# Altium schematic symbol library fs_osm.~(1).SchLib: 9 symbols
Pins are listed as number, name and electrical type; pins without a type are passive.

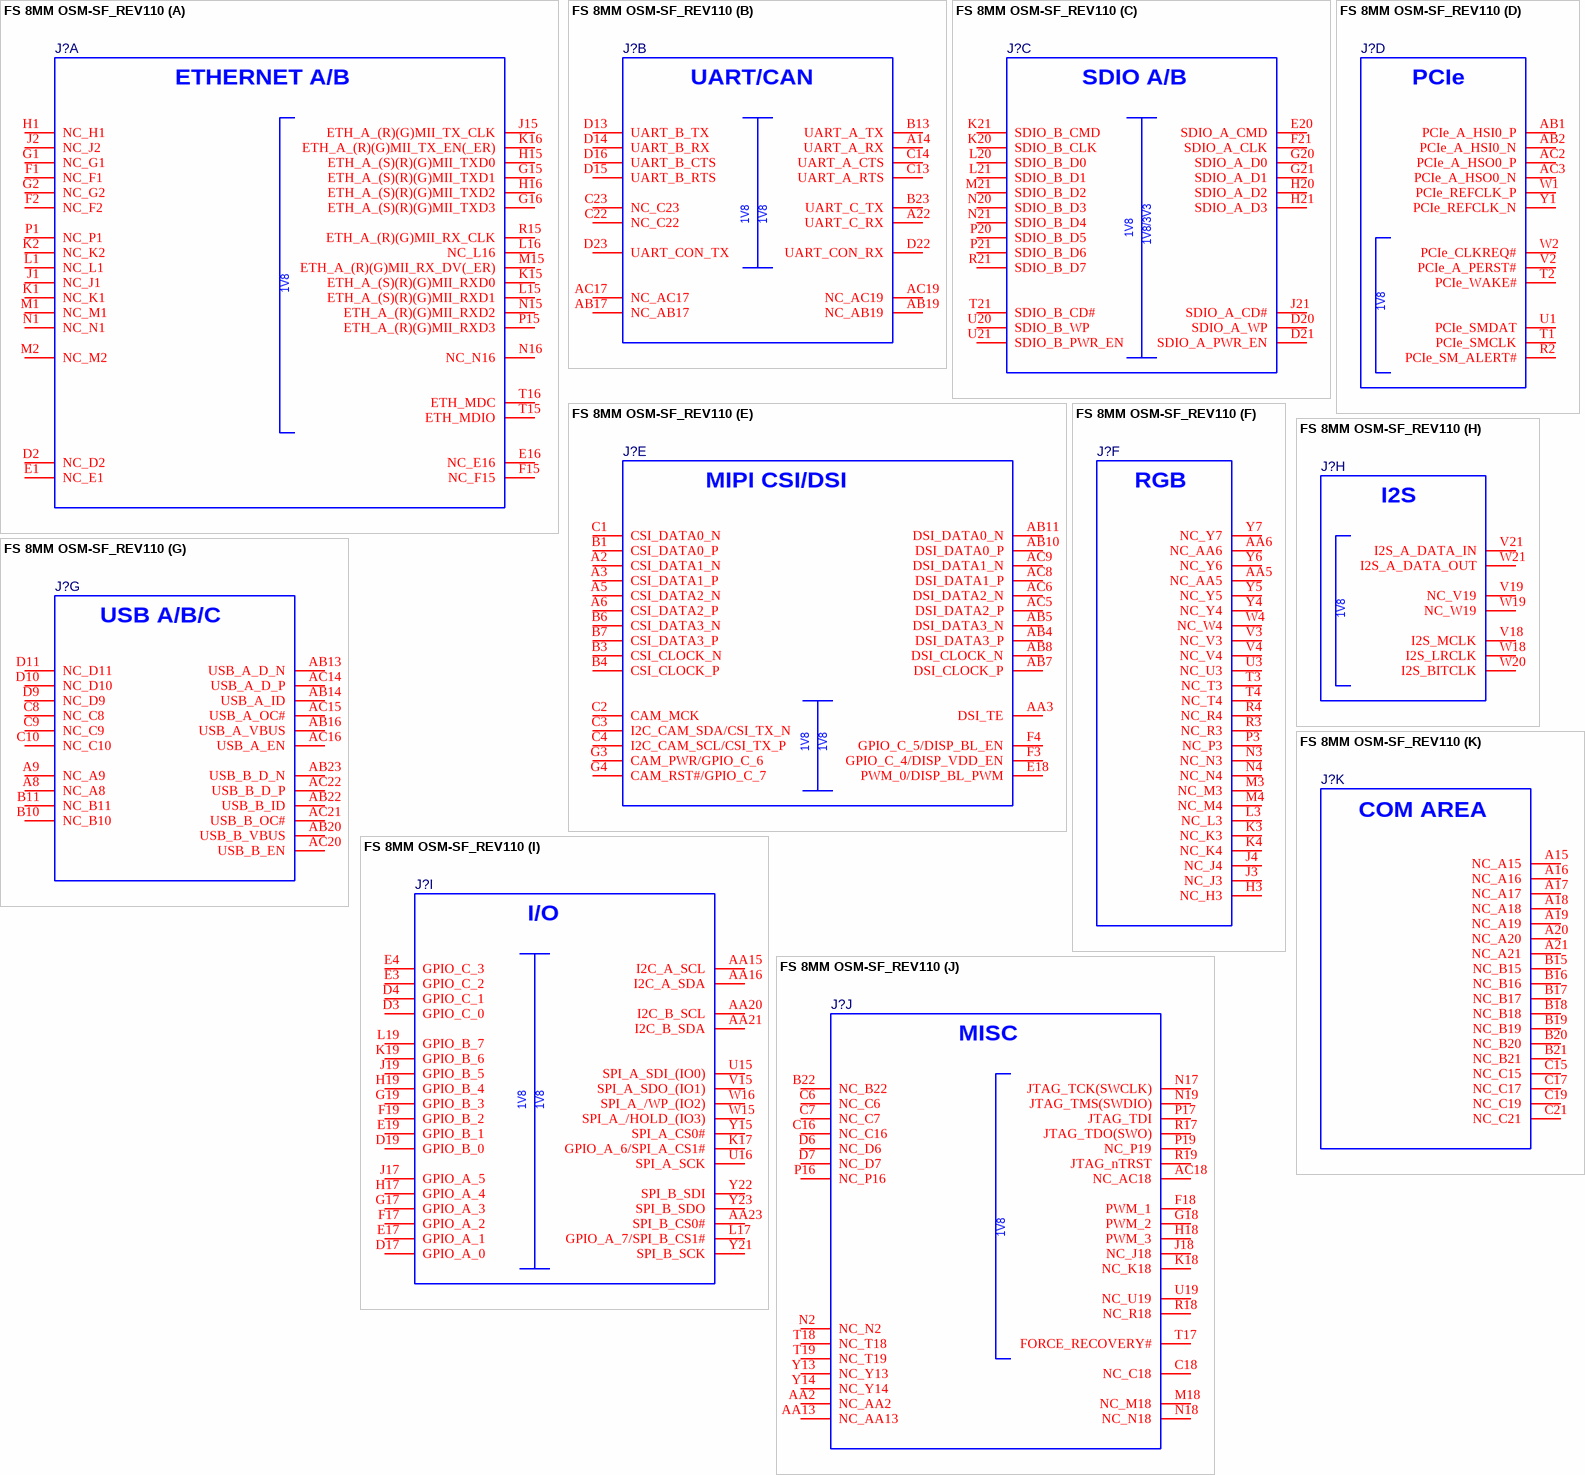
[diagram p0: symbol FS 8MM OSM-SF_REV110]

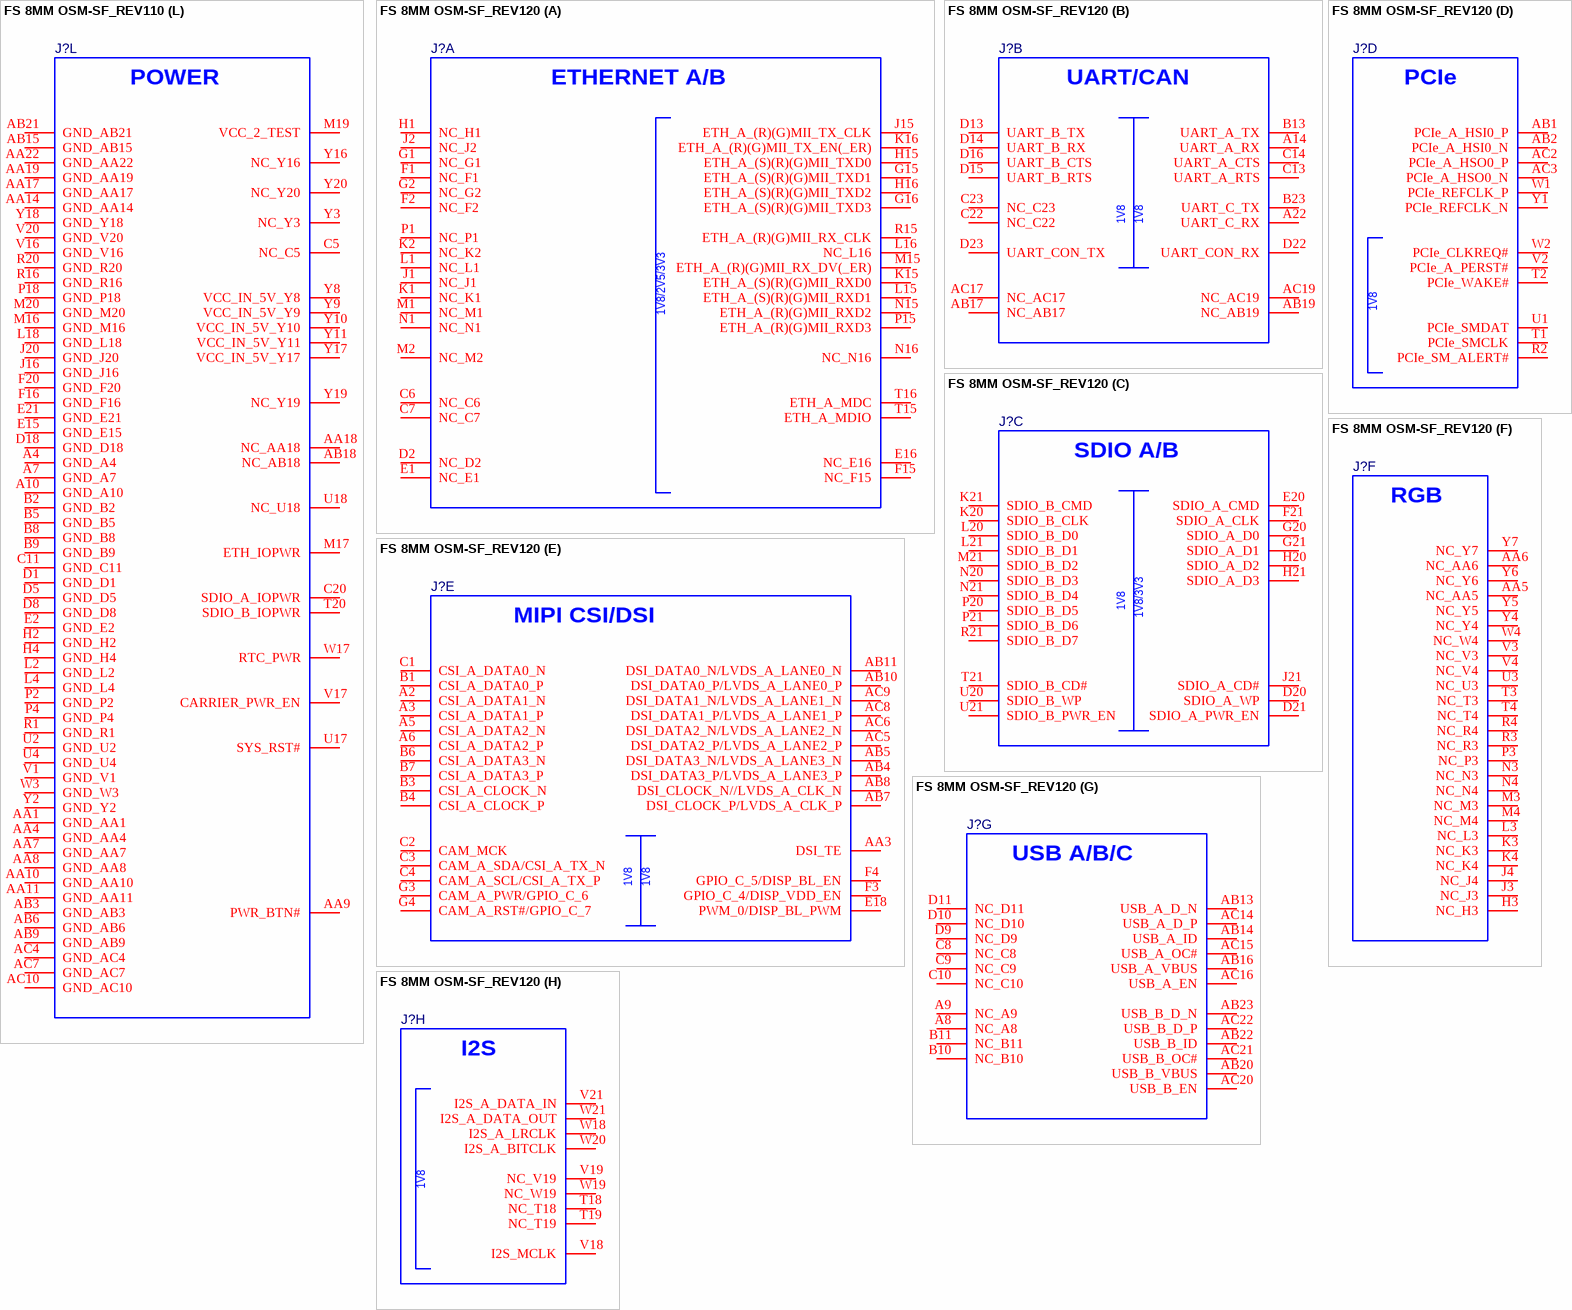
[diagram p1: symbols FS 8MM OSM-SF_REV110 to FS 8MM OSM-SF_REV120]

## FS 8MM OSM-SF_REV110
designator J?  (value not drawn)
part A pins: D2 NC_D2, E1 NC_E1, E16 NC_E16, F1 NC_F1, F2 NC_F2, F15 NC_F15, G1 NC_G1, G2 NC_G2, G15 ETH_A_(S)(R)(G)MII_TXD1, G16 ETH_A_(S)(R)(G)MII_TXD3, H1 NC_H1, H15 ETH_A_(S)(R)(G)MII_TXD0, H16 ETH_A_(S)(R)(G)MII_TXD2, J1 NC_J1, J2 NC_J2, J15 ETH_A_(R)(G)MII_TX_CLK, K1 NC_K1, K2 NC_K2, K15 ETH_A_(S)(R)(G)MII_RXD0, K16 ETH_A_(R)(G)MII_TX_EN(_ER), L1 NC_L1, L15 ETH_A_(S)(R)(G)MII_RXD1, L16 NC_L16, M1 NC_M1, M2 NC_M2, M15 ETH_A_(R)(G)MII_RX_DV(_ER), N1 NC_N1, N15 ETH_A_(R)(G)MII_RXD2, N16 NC_N16, P1 NC_P1, P15 ETH_A_(R)(G)MII_RXD3, R15 ETH_A_(R)(G)MII_RX_CLK, T15 ETH_MDIO, T16 ETH_MDC
part B pins: A14 UART_A_RX, A22 UART_C_RX, AB17 NC_AB17, AB19 NC_AB19, AC17 NC_AC17, AC19 NC_AC19, B13 UART_A_TX, B23 UART_C_TX, C13 UART_A_RTS, C14 UART_A_CTS, C22 NC_C22, C23 NC_C23, D13 UART_B_TX, D14 UART_B_RX, D15 UART_B_RTS, D16 UART_B_CTS, D22 UART_CON_RX, D23 UART_CON_TX
part C pins: D20 SDIO_A_WP, D21 SDIO_A_PWR_EN, E20 SDIO_A_CMD, F21 SDIO_A_CLK, G20 SDIO_A_D0, G21 SDIO_A_D1, H20 SDIO_A_D2, H21 SDIO_A_D3, J21 SDIO_A_CD#, K20 SDIO_B_CLK, K21 SDIO_B_CMD, L20 SDIO_B_D0, L21 SDIO_B_D1, M21 SDIO_B_D2, N20 SDIO_B_D3, N21 SDIO_B_D4, P20 SDIO_B_D5, P21 SDIO_B_D6, R21 SDIO_B_D7, T21 SDIO_B_CD#, U20 SDIO_B_WP, U21 SDIO_B_PWR_EN
part D pins: AB1 PCIe_A_HSI0_P, AB2 PCIe_A_HSI0_N, AC2 PCIe_A_HSO0_P, AC3 PCIe_A_HSO0_N, R2 PCIe_SM_ALERT#, T1 PCIe_SMCLK, T2 PCIe_WAKE#, U1 PCIe_SMDAT, V2 PCIe_A_PERST#, W1 PCIe_REFCLK_P, W2 PCIe_CLKREQ#, Y1 PCIe_REFCLK_N
part E pins: A2 CSI_DATA1_N, A3 CSI_DATA1_P, A5 CSI_DATA2_N, A6 CSI_DATA2_P, AA3 DSI_TE, AB4 DSI_DATA3_P, AB5 DSI_DATA3_N, AB7 DSI_CLOCK_P, AB8 DSI_CLOCK_N, AB10 DSI_DATA0_P, AB11 DSI_DATA0_N, AC5 DSI_DATA2_P, AC6 DSI_DATA2_N, AC8 DSI_DATA1_P, AC9 DSI_DATA1_N, B1 CSI_DATA0_P, B3 CSI_CLOCK_N, B4 CSI_CLOCK_P, B6 CSI_DATA3_N, B7 CSI_DATA3_P, C1 CSI_DATA0_N, C2 CAM_MCK, C3 I2C_CAM_SDA/CSI_TX_N, C4 I2C_CAM_SCL/CSI_TX_P, E18 PWM_0/DISP_BL_PWM, F3 GPIO_C_4/DISP_VDD_EN, F4 GPIO_C_5/DISP_BL_EN, G3 CAM_PWR/GPIO_C_6, G4 CAM_RST#/GPIO_C_7
part F pins: AA5 NC_AA5, AA6 NC_AA6, H3 NC_H3, J3 NC_J3, J4 NC_J4, K3 NC_K3, K4 NC_K4, L3 NC_L3, M3 NC_M3, M4 NC_M4, N3 NC_N3, N4 NC_N4, P3 NC_P3, R3 NC_R3, R4 NC_R4, T3 NC_T3, T4 NC_T4, U3 NC_U3, V3 NC_V3, V4 NC_V4, W4 NC_W4, Y4 NC_Y4, Y5 NC_Y5, Y6 NC_Y6, Y7 NC_Y7
part G pins: A8 NC_A8, A9 NC_A9, AB13 USB_A_D_N, AB14 USB_A_ID, AB16 USB_A_VBUS, AB20 USB_B_VBUS, AB22 USB_B_ID, AB23 USB_B_D_N, AC14 USB_A_D_P, AC15 USB_A_OC#, AC16 USB_A_EN, AC20 USB_B_EN, AC21 USB_B_OC#, AC22 USB_B_D_P, B10 NC_B10, B11 NC_B11, C8 NC_C8, C9 NC_C9, C10 NC_C10, D9 NC_D9, D10 NC_D10, D11 NC_D11
part H pins: V18 I2S_MCLK, V19 NC_V19, V21 I2S_A_DATA_IN, W18 I2S_LRCLK, W19 NC_W19, W20 I2S_BITCLK, W21 I2S_A_DATA_OUT
part I pins: AA15 I2C_A_SCL, AA16 I2C_A_SDA, AA20 I2C_B_SCL, AA21 I2C_B_SDA, AA23 SPI_B_CS0#, D3 GPIO_C_0, D4 GPIO_C_1, D17 GPIO_A_0, D19 GPIO_B_0, E3 GPIO_C_2, E4 GPIO_C_3, E17 GPIO_A_1, E19 GPIO_B_1, F17 GPIO_A_2, F19 GPIO_B_2, G17 GPIO_A_3, G19 GPIO_B_3, H17 GPIO_A_4, H19 GPIO_B_4, J17 GPIO_A_5, J19 GPIO_B_5, K17 GPIO_A_6/SPI_A_CS1#, K19 GPIO_B_6, L17 GPIO_A_7/SPI_B_CS1#, L19 GPIO_B_7, U15 SPI_A_SDI_(IO0), U16 SPI_A_SCK, V15 SPI_A_SDO_(IO1), W15 SPI_A_/HOLD_(IO3), W16 SPI_A_/WP_(IO2), Y15 SPI_A_CS0#, Y21 SPI_B_SCK, Y22 SPI_B_SDI, Y23 SPI_B_SDO
part J pins: AA2 NC_AA2, AA13 NC_AA13, AC18 NC_AC18, B22 NC_B22, C6 NC_C6, C7 NC_C7, C16 NC_C16, C18 NC_C18, D6 NC_D6, D7 NC_D7, F18 PWM_1, G18 PWM_2, H18 PWM_3, J18 NC_J18, K18 NC_K18, M18 NC_M18, N2 NC_N2, N17 JTAG_TCK(SWCLK), N18 NC_N18, N19 JTAG_TMS(SWDIO), P16 NC_P16, P17 JTAG_TDI, P19 NC_P19, R17 JTAG_TDO(SWO), R18 NC_R18, R19 JTAG_nTRST, T17 FORCE_RECOVERY#, T18 NC_T18, T19 NC_T19, U19 NC_U19, Y13 NC_Y13, Y14 NC_Y14
part K pins: A15 NC_A15, A16 NC_A16, A17 NC_A17, A18 NC_A18, A19 NC_A19, A20 NC_A20, A21 NC_A21, B15 NC_B15, B16 NC_B16, B17 NC_B17, B18 NC_B18, B19 NC_B19, B20 NC_B20, B21 NC_B21, C15 NC_C15, C17 NC_C17, C19 NC_C19, C21 NC_C21
part L pins: A4 GND_A4 (power), A7 GND_A7 (power), A10 GND_A10 (power), AA1 GND_AA1 (power), AA4 GND_AA4 (power), AA7 GND_AA7 (power), AA8 GND_AA8 (power), AA9 PWR_BTN#, AA10 GND_AA10 (power), AA11 GND_AA11 (power), AA14 GND_AA14 (power), AA17 GND_AA17 (power), AA18 NC_AA18, AA19 GND_AA19 (power), AA22 GND_AA22 (power), AB3 GND_AB3 (power), AB6 GND_AB6 (power), AB9 GND_AB9 (power), AB15 GND_AB15 (power), AB18 NC_AB18, AB21 GND_AB21 (power), AC4 GND_AC4 (power), AC7 GND_AC7 (power), AC10 GND_AC10 (power), B2 GND_B2 (power), B5 GND_B5 (power), B8 GND_B8 (power), B9 GND_B9 (power), C5 NC_C5, C11 GND_C11 (power), C20 SDIO_A_IOPWR, D1 GND_D1 (power), D5 GND_D5 (power), D8 GND_D8 (power), D18 GND_D18 (power), E2 GND_E2 (power), E15 GND_E15 (power), E21 GND_E21 (power), F16 GND_F16 (power), F20 GND_F20 (power), H2 GND_H2 (power), H4 GND_H4 (power), J16 GND_J16 (power), J20 GND_J20 (power), L2 GND_L2 (power), L4 GND_L4 (power), L18 GND_L18 (power), M16 GND_M16 (power), M17 ETH_IOPWR (power), M19 VCC_2_TEST, M20 GND_M20 (power), P2 GND_P2 (power), P4 GND_P4 (power), P18 GND_P18 (power), R1 GND_R1 (power), R16 GND_R16 (power), R20 GND_R20 (power), T20 SDIO_B_IOPWR, U2 GND_U2 (power), U4 GND_U4 (power), U17 SYS_RST#, U18 NC_U18, V1 GND_V1 (power), V16 GND_V16 (power), V17 CARRIER_PWR_EN, V20 GND_V20 (power), W3 GND_W3 (power), W17 RTC_PWR (power), Y2 GND_Y2 (power), Y3 NC_Y3, Y8 VCC_IN_5V_Y8 (power), Y9 VCC_IN_5V_Y9 (power), Y10 VCC_IN_5V_Y10 (power), Y11 VCC_IN_5V_Y11 (power), Y16 NC_Y16, Y17 VCC_IN_5V_Y17 (power), Y18 GND_Y18 (power), Y19 NC_Y19, Y20 NC_Y20

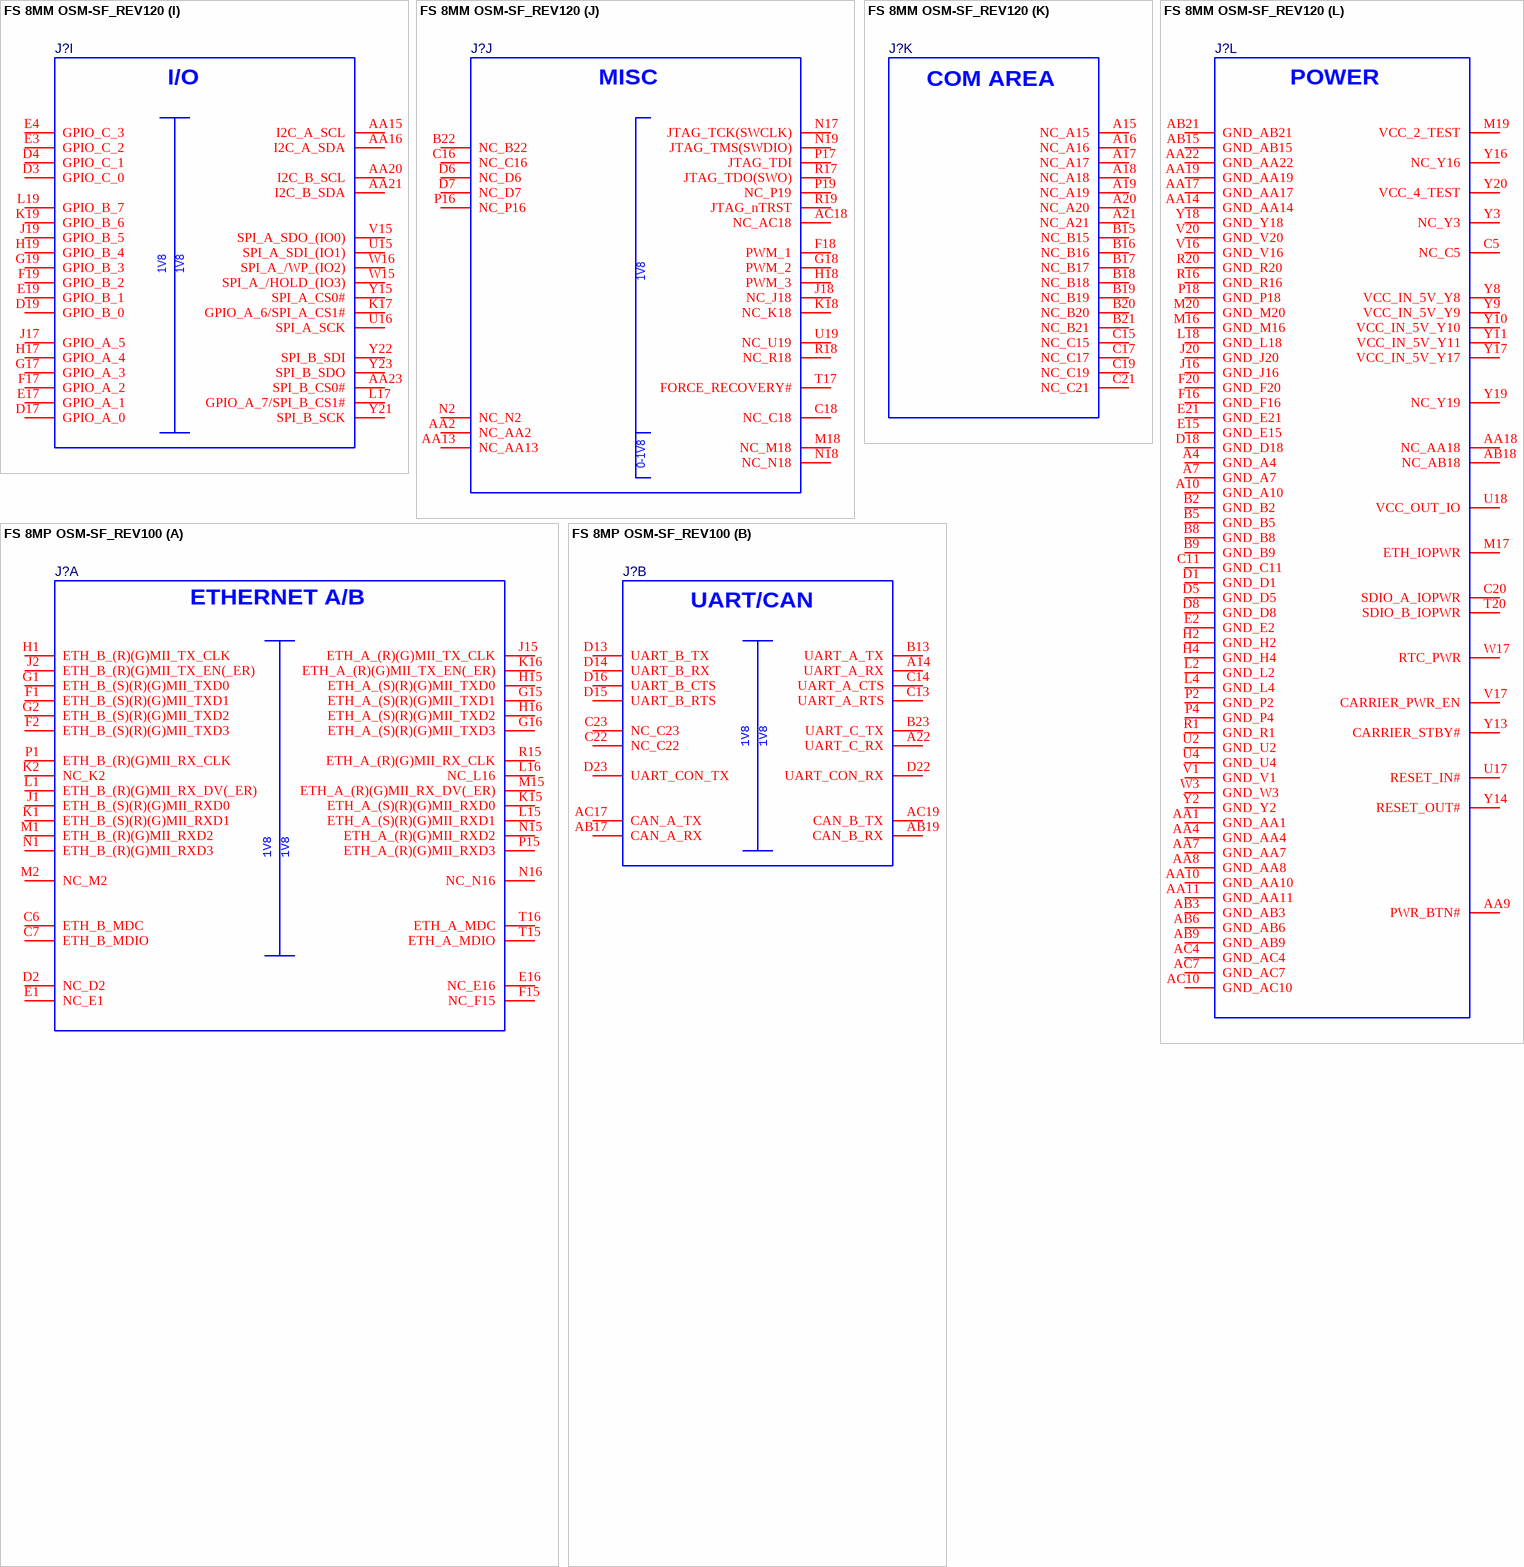
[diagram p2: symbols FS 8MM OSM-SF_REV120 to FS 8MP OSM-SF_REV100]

## FS 8MM OSM-SF_REV120
designator J?  (value not drawn)
part A pins: C6 NC_C6, C7 NC_C7, D2 NC_D2, E1 NC_E1, E16 NC_E16, F1 NC_F1, F2 NC_F2, F15 NC_F15, G1 NC_G1, G2 NC_G2, G15 ETH_A_(S)(R)(G)MII_TXD1, G16 ETH_A_(S)(R)(G)MII_TXD3, H1 NC_H1, H15 ETH_A_(S)(R)(G)MII_TXD0, H16 ETH_A_(S)(R)(G)MII_TXD2, J1 NC_J1, J2 NC_J2, J15 ETH_A_(R)(G)MII_TX_CLK, K1 NC_K1, K2 NC_K2, K15 ETH_A_(S)(R)(G)MII_RXD0, K16 ETH_A_(R)(G)MII_TX_EN(_ER), L1 NC_L1, L15 ETH_A_(S)(R)(G)MII_RXD1, L16 NC_L16, M1 NC_M1, M2 NC_M2, M15 ETH_A_(R)(G)MII_RX_DV(_ER), N1 NC_N1, N15 ETH_A_(R)(G)MII_RXD2, N16 NC_N16, P1 NC_P1, P15 ETH_A_(R)(G)MII_RXD3, R15 ETH_A_(R)(G)MII_RX_CLK, T15 ETH_A_MDIO, T16 ETH_A_MDC
part B pins: A14 UART_A_RX, A22 UART_C_RX, AB17 NC_AB17, AB19 NC_AB19, AC17 NC_AC17, AC19 NC_AC19, B13 UART_A_TX, B23 UART_C_TX, C13 UART_A_RTS, C14 UART_A_CTS, C22 NC_C22, C23 NC_C23, D13 UART_B_TX, D14 UART_B_RX, D15 UART_B_RTS, D16 UART_B_CTS, D22 UART_CON_RX, D23 UART_CON_TX
part C pins: D20 SDIO_A_WP, D21 SDIO_A_PWR_EN, E20 SDIO_A_CMD, F21 SDIO_A_CLK, G20 SDIO_A_D0, G21 SDIO_A_D1, H20 SDIO_A_D2, H21 SDIO_A_D3, J21 SDIO_A_CD#, K20 SDIO_B_CLK, K21 SDIO_B_CMD, L20 SDIO_B_D0, L21 SDIO_B_D1, M21 SDIO_B_D2, N20 SDIO_B_D3, N21 SDIO_B_D4, P20 SDIO_B_D5, P21 SDIO_B_D6, R21 SDIO_B_D7, T21 SDIO_B_CD#, U20 SDIO_B_WP, U21 SDIO_B_PWR_EN
part D pins: AB1 PCIe_A_HSI0_P, AB2 PCIe_A_HSI0_N, AC2 PCIe_A_HSO0_P, AC3 PCIe_A_HSO0_N, R2 PCIe_SM_ALERT#, T1 PCIe_SMCLK, T2 PCIe_WAKE#, U1 PCIe_SMDAT, V2 PCIe_A_PERST#, W1 PCIe_REFCLK_P, W2 PCIe_CLKREQ#, Y1 PCIe_REFCLK_N
part E pins: A2 CSI_A_DATA1_N, A3 CSI_A_DATA1_P, A5 CSI_A_DATA2_N, A6 CSI_A_DATA2_P, AA3 DSI_TE, AB4 DSI_DATA3_P/LVDS_A_LANE3_P, AB5 DSI_DATA3_N/LVDS_A_LANE3_N, AB7 DSI_CLOCK_P/LVDS_A_CLK_P, AB8 DSI_CLOCK_N//LVDS_A_CLK_N, AB10 DSI_DATA0_P/LVDS_A_LANE0_P, AB11 DSI_DATA0_N/LVDS_A_LANE0_N, AC5 DSI_DATA2_P/LVDS_A_LANE2_P, AC6 DSI_DATA2_N/LVDS_A_LANE2_N, AC8 DSI_DATA1_P/LVDS_A_LANE1_P, AC9 DSI_DATA1_N/LVDS_A_LANE1_N, B1 CSI_A_DATA0_P, B3 CSI_A_CLOCK_N, B4 CSI_A_CLOCK_P, B6 CSI_A_DATA3_N, B7 CSI_A_DATA3_P, C1 CSI_A_DATA0_N, C2 CAM_MCK, C3 CAM_A_SDA/CSI_A_TX_N, C4 CAM_A_SCL/CSI_A_TX_P, E18 PWM_0/DISP_BL_PWM, F3 GPIO_C_4/DISP_VDD_EN, F4 GPIO_C_5/DISP_BL_EN, G3 CAM_A_PWR/GPIO_C_6, G4 CAM_A_RST#/GPIO_C_7
part F pins: AA5 NC_AA5, AA6 NC_AA6, H3 NC_H3, J3 NC_J3, J4 NC_J4, K3 NC_K3, K4 NC_K4, L3 NC_L3, M3 NC_M3, M4 NC_M4, N3 NC_N3, N4 NC_N4, P3 NC_P3, R3 NC_R3, R4 NC_R4, T3 NC_T3, T4 NC_T4, U3 NC_U3, V3 NC_V3, V4 NC_V4, W4 NC_W4, Y4 NC_Y4, Y5 NC_Y5, Y6 NC_Y6, Y7 NC_Y7
part G pins: A8 NC_A8, A9 NC_A9, AB13 USB_A_D_N, AB14 USB_A_ID, AB16 USB_A_VBUS, AB20 USB_B_VBUS, AB22 USB_B_ID, AB23 USB_B_D_N, AC14 USB_A_D_P, AC15 USB_A_OC#, AC16 USB_A_EN, AC20 USB_B_EN, AC21 USB_B_OC#, AC22 USB_B_D_P, B10 NC_B10, B11 NC_B11, C8 NC_C8, C9 NC_C9, C10 NC_C10, D9 NC_D9, D10 NC_D10, D11 NC_D11
part H pins: T18 NC_T18, T19 NC_T19, V18 I2S_MCLK, V19 NC_V19, V21 I2S_A_DATA_IN, W18 I2S_A_LRCLK, W19 NC_W19, W20 I2S_A_BITCLK, W21 I2S_A_DATA_OUT
part I pins: AA15 I2C_A_SCL, AA16 I2C_A_SDA, AA20 I2C_B_SCL, AA21 I2C_B_SDA, AA23 SPI_B_CS0#, D3 GPIO_C_0, D4 GPIO_C_1, D17 GPIO_A_0, D19 GPIO_B_0, E3 GPIO_C_2, E4 GPIO_C_3, E17 GPIO_A_1, E19 GPIO_B_1, F17 GPIO_A_2, F19 GPIO_B_2, G17 GPIO_A_3, G19 GPIO_B_3, H17 GPIO_A_4, H19 GPIO_B_4, J17 GPIO_A_5, J19 GPIO_B_5, K17 GPIO_A_6/SPI_A_CS1#, K19 GPIO_B_6, L17 GPIO_A_7/SPI_B_CS1#, L19 GPIO_B_7, U15 SPI_A_SDI_(IO1), U16 SPI_A_SCK, V15 SPI_A_SDO_(IO0), W15 SPI_A_/HOLD_(IO3), W16 SPI_A_/WP_(IO2), Y15 SPI_A_CS0#, Y21 SPI_B_SCK, Y22 SPI_B_SDI, Y23 SPI_B_SDO
part J pins: AA2 NC_AA2, AA13 NC_AA13, AC18 NC_AC18, B22 NC_B22, C16 NC_C16, C18 NC_C18, D6 NC_D6, D7 NC_D7, F18 PWM_1, G18 PWM_2, H18 PWM_3, J18 NC_J18, K18 NC_K18, M18 NC_M18, N2 NC_N2, N17 JTAG_TCK(SWCLK), N18 NC_N18, N19 JTAG_TMS(SWDIO), P16 NC_P16, P17 JTAG_TDI, P19 NC_P19, R17 JTAG_TDO(SWO), R18 NC_R18, R19 JTAG_nTRST, T17 FORCE_RECOVERY#, U19 NC_U19
part K pins: A15 NC_A15, A16 NC_A16, A17 NC_A17, A18 NC_A18, A19 NC_A19, A20 NC_A20, A21 NC_A21, B15 NC_B15, B16 NC_B16, B17 NC_B17, B18 NC_B18, B19 NC_B19, B20 NC_B20, B21 NC_B21, C15 NC_C15, C17 NC_C17, C19 NC_C19, C21 NC_C21
part L pins: A4 GND_A4 (power), A7 GND_A7 (power), A10 GND_A10 (power), AA1 GND_AA1 (power), AA4 GND_AA4 (power), AA7 GND_AA7 (power), AA8 GND_AA8 (power), AA9 PWR_BTN#, AA10 GND_AA10 (power), AA11 GND_AA11 (power), AA14 GND_AA14 (power), AA17 GND_AA17 (power), AA18 NC_AA18, AA19 GND_AA19 (power), AA22 GND_AA22 (power), AB3 GND_AB3 (power), AB6 GND_AB6 (power), AB9 GND_AB9 (power), AB15 GND_AB15 (power), AB18 NC_AB18, AB21 GND_AB21 (power), AC4 GND_AC4 (power), AC7 GND_AC7 (power), AC10 GND_AC10 (power), B2 GND_B2 (power), B5 GND_B5 (power), B8 GND_B8 (power), B9 GND_B9 (power), C5 NC_C5, C11 GND_C11 (power), C20 SDIO_A_IOPWR, D1 GND_D1 (power), D5 GND_D5 (power), D8 GND_D8 (power), D18 GND_D18 (power), E2 GND_E2 (power), E15 GND_E15 (power), E21 GND_E21 (power), F16 GND_F16 (power), F20 GND_F20 (power), H2 GND_H2 (power), H4 GND_H4 (power), J16 GND_J16 (power), J20 GND_J20 (power), L2 GND_L2 (power), L4 GND_L4 (power), L18 GND_L18 (power), M16 GND_M16 (power), M17 ETH_IOPWR (power), M19 VCC_2_TEST, M20 GND_M20 (power), P2 GND_P2 (power), P4 GND_P4 (power), P18 GND_P18 (power), R1 GND_R1 (power), R16 GND_R16 (power), R20 GND_R20 (power), T20 SDIO_B_IOPWR, U2 GND_U2 (power), U4 GND_U4 (power), U17 RESET_IN#, U18 VCC_OUT_IO, V1 GND_V1 (power), V16 GND_V16 (power), V17 CARRIER_PWR_EN, V20 GND_V20 (power), W3 GND_W3 (power), W17 RTC_PWR (power), Y2 GND_Y2 (power), Y3 NC_Y3, Y8 VCC_IN_5V_Y8 (power), Y9 VCC_IN_5V_Y9 (power), Y10 VCC_IN_5V_Y10 (power), Y11 VCC_IN_5V_Y11 (power), Y13 CARRIER_STBY#, Y14 RESET_OUT#, Y16 NC_Y16, Y17 VCC_IN_5V_Y17 (power), Y18 GND_Y18 (power), Y19 NC_Y19, Y20 VCC_4_TEST

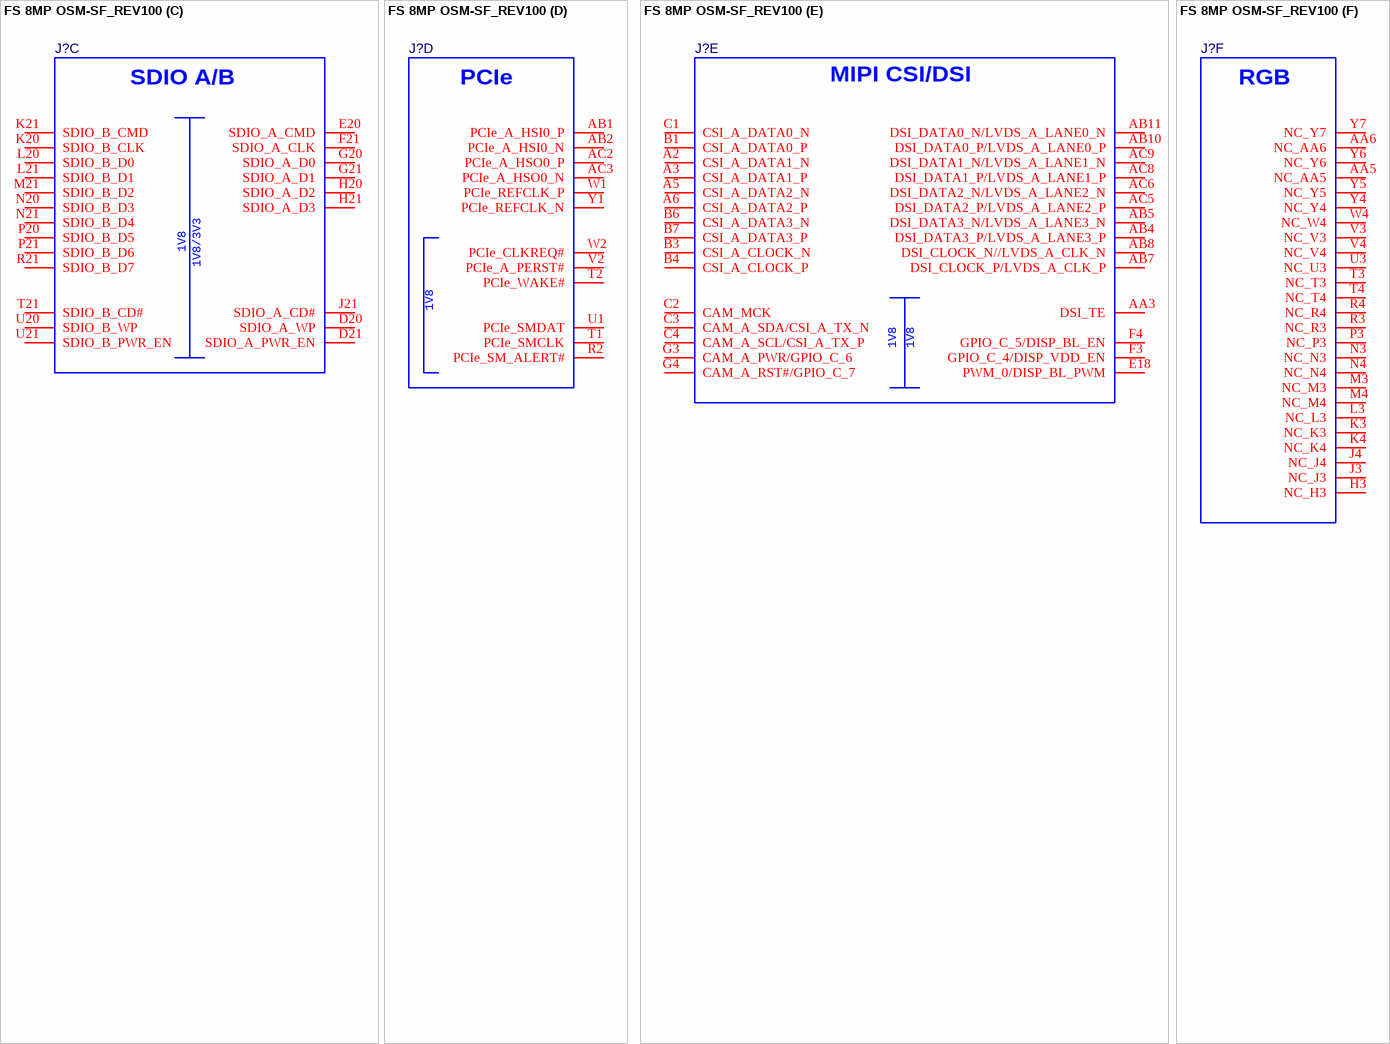
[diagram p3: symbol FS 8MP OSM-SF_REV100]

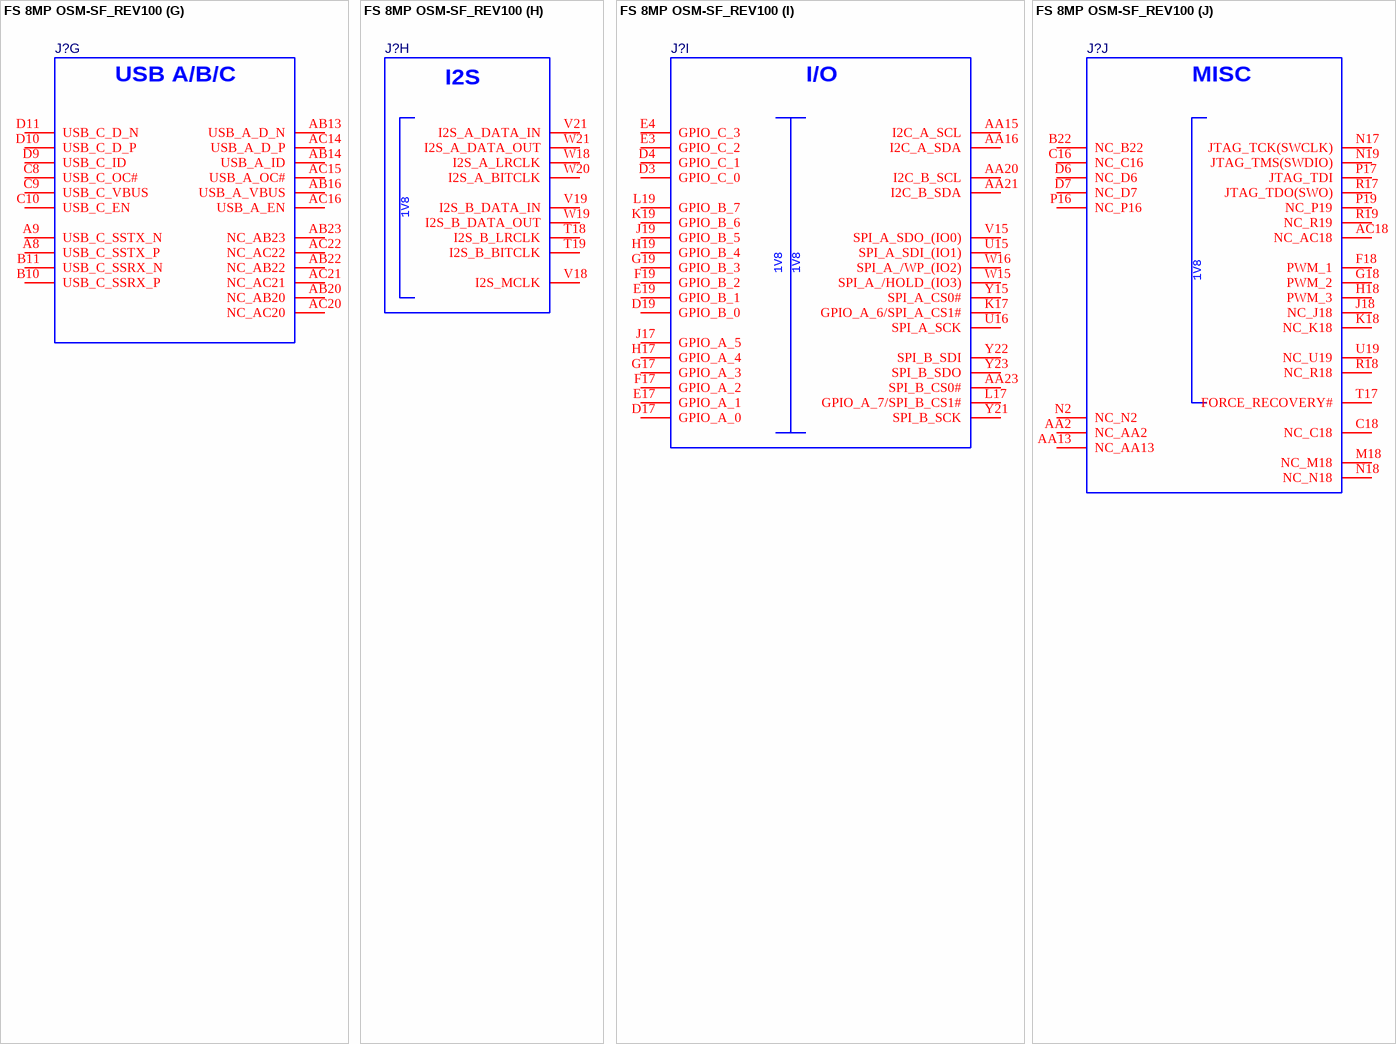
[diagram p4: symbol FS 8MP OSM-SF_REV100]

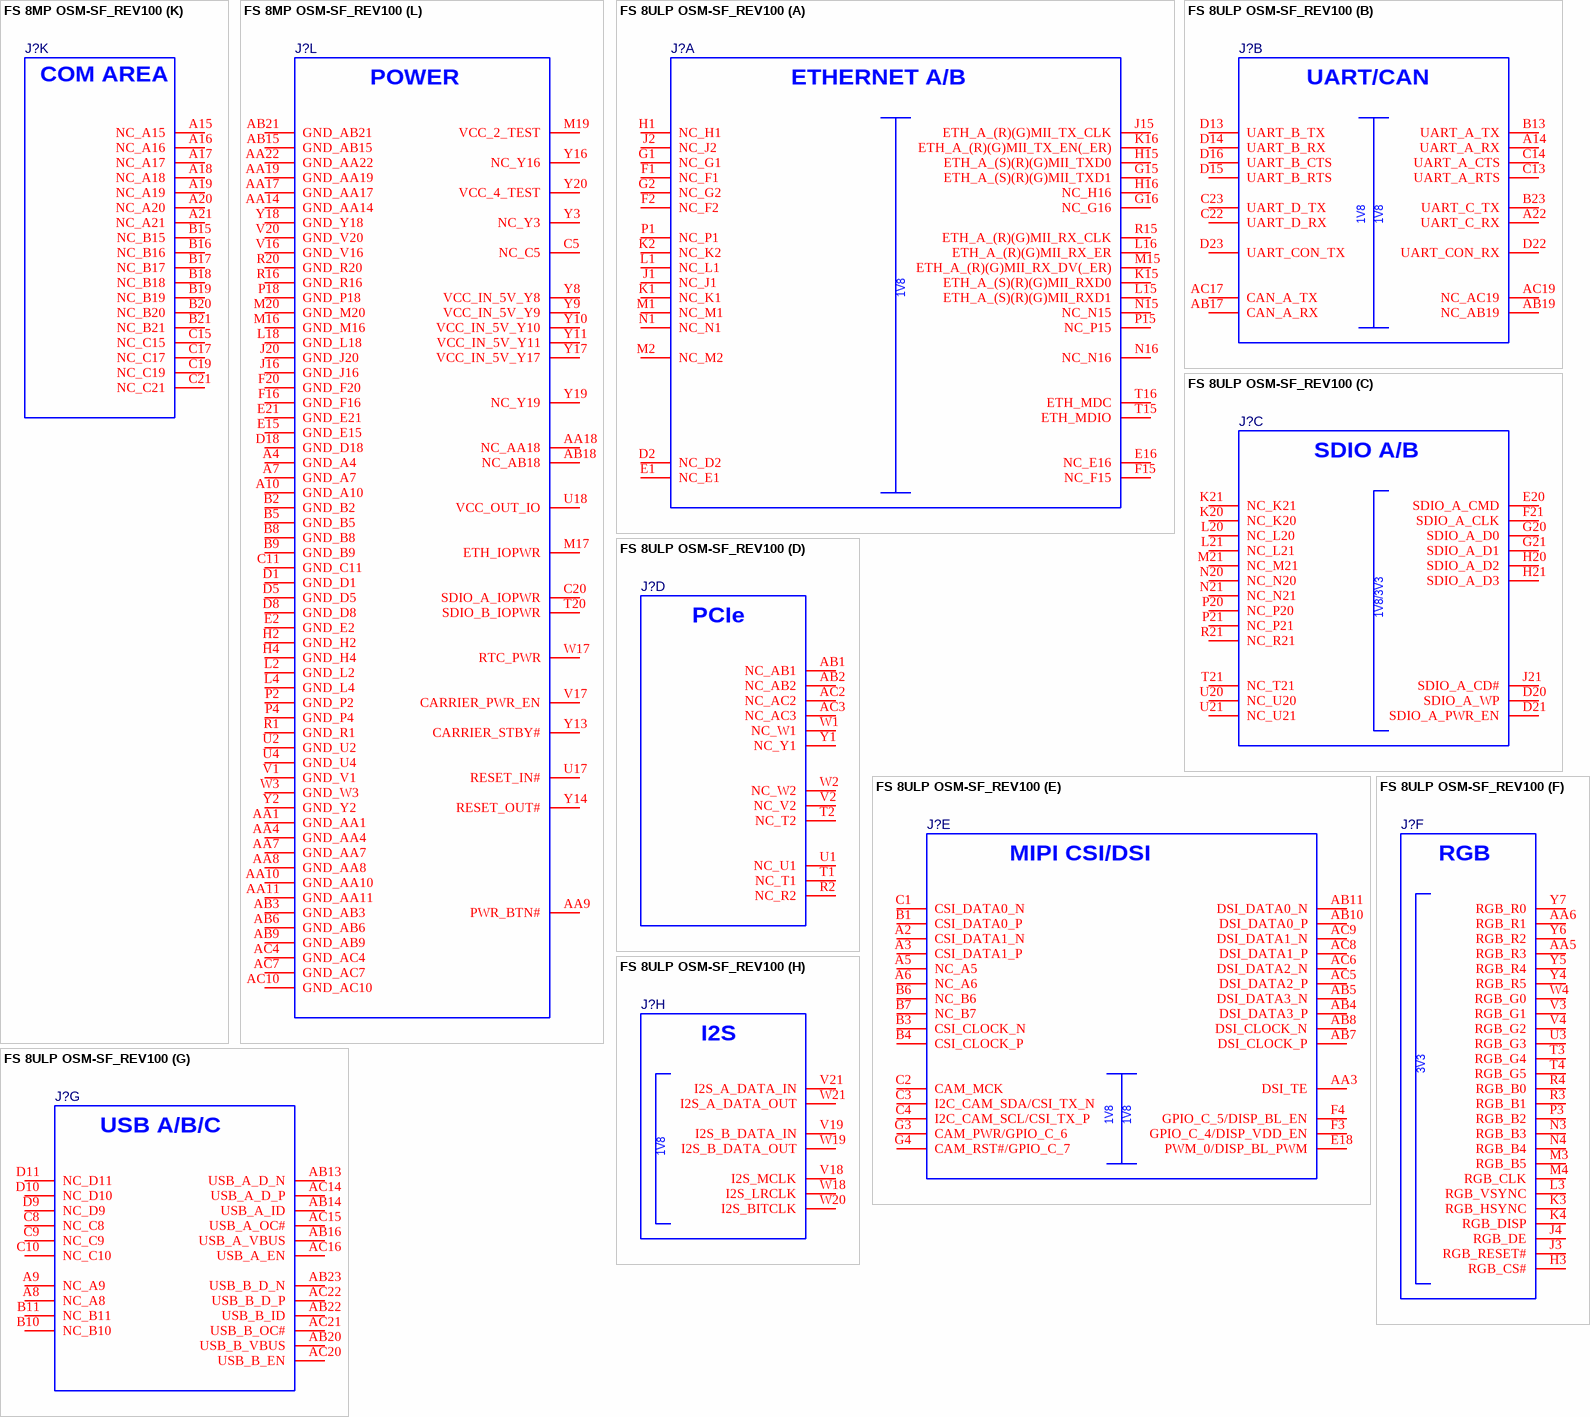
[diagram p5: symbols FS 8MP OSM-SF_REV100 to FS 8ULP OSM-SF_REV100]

## FS 8MP OSM-SF_REV100
designator J?  (value not drawn)
part A pins: C6 ETH_B_MDC, C7 ETH_B_MDIO, D2 NC_D2, E1 NC_E1, E16 NC_E16, F1 ETH_B_(S)(R)(G)MII_TXD1, F2 ETH_B_(S)(R)(G)MII_TXD3, F15 NC_F15, G1 ETH_B_(S)(R)(G)MII_TXD0, G2 ETH_B_(S)(R)(G)MII_TXD2, G15 ETH_A_(S)(R)(G)MII_TXD1, G16 ETH_A_(S)(R)(G)MII_TXD3, H1 ETH_B_(R)(G)MII_TX_CLK, H15 ETH_A_(S)(R)(G)MII_TXD0, H16 ETH_A_(S)(R)(G)MII_TXD2, J1 ETH_B_(S)(R)(G)MII_RXD0, J2 ETH_B_(R)(G)MII_TX_EN(_ER), J15 ETH_A_(R)(G)MII_TX_CLK, K1 ETH_B_(S)(R)(G)MII_RXD1, K2 NC_K2, K15 ETH_A_(S)(R)(G)MII_RXD0, K16 ETH_A_(R)(G)MII_TX_EN(_ER), L1 ETH_B_(R)(G)MII_RX_DV(_ER), L15 ETH_A_(S)(R)(G)MII_RXD1, L16 NC_L16, M1 ETH_B_(R)(G)MII_RXD2, M2 NC_M2, M15 ETH_A_(R)(G)MII_RX_DV(_ER), N1 ETH_B_(R)(G)MII_RXD3, N15 ETH_A_(R)(G)MII_RXD2, N16 NC_N16, P1 ETH_B_(R)(G)MII_RX_CLK, P15 ETH_A_(R)(G)MII_RXD3, R15 ETH_A_(R)(G)MII_RX_CLK, T15 ETH_A_MDIO, T16 ETH_A_MDC
part B pins: A14 UART_A_RX, A22 UART_C_RX, AB17 CAN_A_RX, AB19 CAN_B_RX, AC17 CAN_A_TX, AC19 CAN_B_TX, B13 UART_A_TX, B23 UART_C_TX, C13 UART_A_RTS, C14 UART_A_CTS, C22 NC_C22, C23 NC_C23, D13 UART_B_TX, D14 UART_B_RX, D15 UART_B_RTS, D16 UART_B_CTS, D22 UART_CON_RX, D23 UART_CON_TX
part C pins: D20 SDIO_A_WP, D21 SDIO_A_PWR_EN, E20 SDIO_A_CMD, F21 SDIO_A_CLK, G20 SDIO_A_D0, G21 SDIO_A_D1, H20 SDIO_A_D2, H21 SDIO_A_D3, J21 SDIO_A_CD#, K20 SDIO_B_CLK, K21 SDIO_B_CMD, L20 SDIO_B_D0, L21 SDIO_B_D1, M21 SDIO_B_D2, N20 SDIO_B_D3, N21 SDIO_B_D4, P20 SDIO_B_D5, P21 SDIO_B_D6, R21 SDIO_B_D7, T21 SDIO_B_CD#, U20 SDIO_B_WP, U21 SDIO_B_PWR_EN
part D pins: AB1 PCIe_A_HSI0_P, AB2 PCIe_A_HSI0_N, AC2 PCIe_A_HSO0_P, AC3 PCIe_A_HSO0_N, R2 PCIe_SM_ALERT#, T1 PCIe_SMCLK, T2 PCIe_WAKE#, U1 PCIe_SMDAT, V2 PCIe_A_PERST#, W1 PCIe_REFCLK_P, W2 PCIe_CLKREQ#, Y1 PCIe_REFCLK_N
part E pins: A2 CSI_A_DATA1_N, A3 CSI_A_DATA1_P, A5 CSI_A_DATA2_N, A6 CSI_A_DATA2_P, AA3 DSI_TE, AB4 DSI_DATA3_P/LVDS_A_LANE3_P, AB5 DSI_DATA3_N/LVDS_A_LANE3_N, AB7 DSI_CLOCK_P/LVDS_A_CLK_P, AB8 DSI_CLOCK_N//LVDS_A_CLK_N, AB10 DSI_DATA0_P/LVDS_A_LANE0_P, AB11 DSI_DATA0_N/LVDS_A_LANE0_N, AC5 DSI_DATA2_P/LVDS_A_LANE2_P, AC6 DSI_DATA2_N/LVDS_A_LANE2_N, AC8 DSI_DATA1_P/LVDS_A_LANE1_P, AC9 DSI_DATA1_N/LVDS_A_LANE1_N, B1 CSI_A_DATA0_P, B3 CSI_A_CLOCK_N, B4 CSI_A_CLOCK_P, B6 CSI_A_DATA3_N, B7 CSI_A_DATA3_P, C1 CSI_A_DATA0_N, C2 CAM_MCK, C3 CAM_A_SDA/CSI_A_TX_N, C4 CAM_A_SCL/CSI_A_TX_P, E18 PWM_0/DISP_BL_PWM, F3 GPIO_C_4/DISP_VDD_EN, F4 GPIO_C_5/DISP_BL_EN, G3 CAM_A_PWR/GPIO_C_6, G4 CAM_A_RST#/GPIO_C_7
part F pins: AA5 NC_AA5, AA6 NC_AA6, H3 NC_H3, J3 NC_J3, J4 NC_J4, K3 NC_K3, K4 NC_K4, L3 NC_L3, M3 NC_M3, M4 NC_M4, N3 NC_N3, N4 NC_N4, P3 NC_P3, R3 NC_R3, R4 NC_R4, T3 NC_T3, T4 NC_T4, U3 NC_U3, V3 NC_V3, V4 NC_V4, W4 NC_W4, Y4 NC_Y4, Y5 NC_Y5, Y6 NC_Y6, Y7 NC_Y7
part G pins: A8 USB_C_SSTX_P, A9 USB_C_SSTX_N, AB13 USB_A_D_N, AB14 USB_A_ID, AB16 USB_A_VBUS, AB20 NC_AB20, AB22 NC_AB22, AB23 NC_AB23, AC14 USB_A_D_P, AC15 USB_A_OC#, AC16 USB_A_EN, AC20 NC_AC20, AC21 NC_AC21, AC22 NC_AC22, B10 USB_C_SSRX_P, B11 USB_C_SSRX_N, C8 USB_C_OC#, C9 USB_C_VBUS, C10 USB_C_EN, D9 USB_C_ID, D10 USB_C_D_P, D11 USB_C_D_N
part H pins: T18 I2S_B_LRCLK, T19 I2S_B_BITCLK, V18 I2S_MCLK, V19 I2S_B_DATA_IN, V21 I2S_A_DATA_IN, W18 I2S_A_LRCLK, W19 I2S_B_DATA_OUT, W20 I2S_A_BITCLK, W21 I2S_A_DATA_OUT
part I pins: AA15 I2C_A_SCL, AA16 I2C_A_SDA, AA20 I2C_B_SCL, AA21 I2C_B_SDA, AA23 SPI_B_CS0#, D3 GPIO_C_0, D4 GPIO_C_1, D17 GPIO_A_0, D19 GPIO_B_0, E3 GPIO_C_2, E4 GPIO_C_3, E17 GPIO_A_1, E19 GPIO_B_1, F17 GPIO_A_2, F19 GPIO_B_2, G17 GPIO_A_3, G19 GPIO_B_3, H17 GPIO_A_4, H19 GPIO_B_4, J17 GPIO_A_5, J19 GPIO_B_5, K17 GPIO_A_6/SPI_A_CS1#, K19 GPIO_B_6, L17 GPIO_A_7/SPI_B_CS1#, L19 GPIO_B_7, U15 SPI_A_SDI_(IO1), U16 SPI_A_SCK, V15 SPI_A_SDO_(IO0), W15 SPI_A_/HOLD_(IO3), W16 SPI_A_/WP_(IO2), Y15 SPI_A_CS0#, Y21 SPI_B_SCK, Y22 SPI_B_SDI, Y23 SPI_B_SDO
part J pins: AA2 NC_AA2, AA13 NC_AA13, AC18 NC_AC18, B22 NC_B22, C16 NC_C16, C18 NC_C18, D6 NC_D6, D7 NC_D7, F18 PWM_1, G18 PWM_2, H18 PWM_3, J18 NC_J18, K18 NC_K18, M18 NC_M18, N2 NC_N2, N17 JTAG_TCK(SWCLK), N18 NC_N18, N19 JTAG_TMS(SWDIO), P16 NC_P16, P17 JTAG_TDI, P19 NC_P19, R17 JTAG_TDO(SWO), R18 NC_R18, R19 NC_R19, T17 FORCE_RECOVERY#, U19 NC_U19
part K pins: A15 NC_A15, A16 NC_A16, A17 NC_A17, A18 NC_A18, A19 NC_A19, A20 NC_A20, A21 NC_A21, B15 NC_B15, B16 NC_B16, B17 NC_B17, B18 NC_B18, B19 NC_B19, B20 NC_B20, B21 NC_B21, C15 NC_C15, C17 NC_C17, C19 NC_C19, C21 NC_C21
part L pins: A4 GND_A4 (power), A7 GND_A7 (power), A10 GND_A10 (power), AA1 GND_AA1 (power), AA4 GND_AA4 (power), AA7 GND_AA7 (power), AA8 GND_AA8 (power), AA9 PWR_BTN#, AA10 GND_AA10 (power), AA11 GND_AA11 (power), AA14 GND_AA14 (power), AA17 GND_AA17 (power), AA18 NC_AA18, AA19 GND_AA19 (power), AA22 GND_AA22 (power), AB3 GND_AB3 (power), AB6 GND_AB6 (power), AB9 GND_AB9 (power), AB15 GND_AB15 (power), AB18 NC_AB18, AB21 GND_AB21 (power), AC4 GND_AC4 (power), AC7 GND_AC7 (power), AC10 GND_AC10 (power), B2 GND_B2 (power), B5 GND_B5 (power), B8 GND_B8 (power), B9 GND_B9 (power), C5 NC_C5, C11 GND_C11 (power), C20 SDIO_A_IOPWR, D1 GND_D1 (power), D5 GND_D5 (power), D8 GND_D8 (power), D18 GND_D18 (power), E2 GND_E2 (power), E15 GND_E15 (power), E21 GND_E21 (power), F16 GND_F16 (power), F20 GND_F20 (power), H2 GND_H2 (power), H4 GND_H4 (power), J16 GND_J16 (power), J20 GND_J20 (power), L2 GND_L2 (power), L4 GND_L4 (power), L18 GND_L18 (power), M16 GND_M16 (power), M17 ETH_IOPWR (power), M19 VCC_2_TEST, M20 GND_M20 (power), P2 GND_P2 (power), P4 GND_P4 (power), P18 GND_P18 (power), R1 GND_R1 (power), R16 GND_R16 (power), R20 GND_R20 (power), T20 SDIO_B_IOPWR, U2 GND_U2 (power), U4 GND_U4 (power), U17 RESET_IN#, U18 VCC_OUT_IO, V1 GND_V1 (power), V16 GND_V16 (power), V17 CARRIER_PWR_EN, V20 GND_V20 (power), W3 GND_W3 (power), W17 RTC_PWR (power), Y2 GND_Y2 (power), Y3 NC_Y3, Y8 VCC_IN_5V_Y8 (power), Y9 VCC_IN_5V_Y9 (power), Y10 VCC_IN_5V_Y10 (power), Y11 VCC_IN_5V_Y11 (power), Y13 CARRIER_STBY#, Y14 RESET_OUT#, Y16 NC_Y16, Y17 VCC_IN_5V_Y17 (power), Y18 GND_Y18 (power), Y19 NC_Y19, Y20 VCC_4_TEST

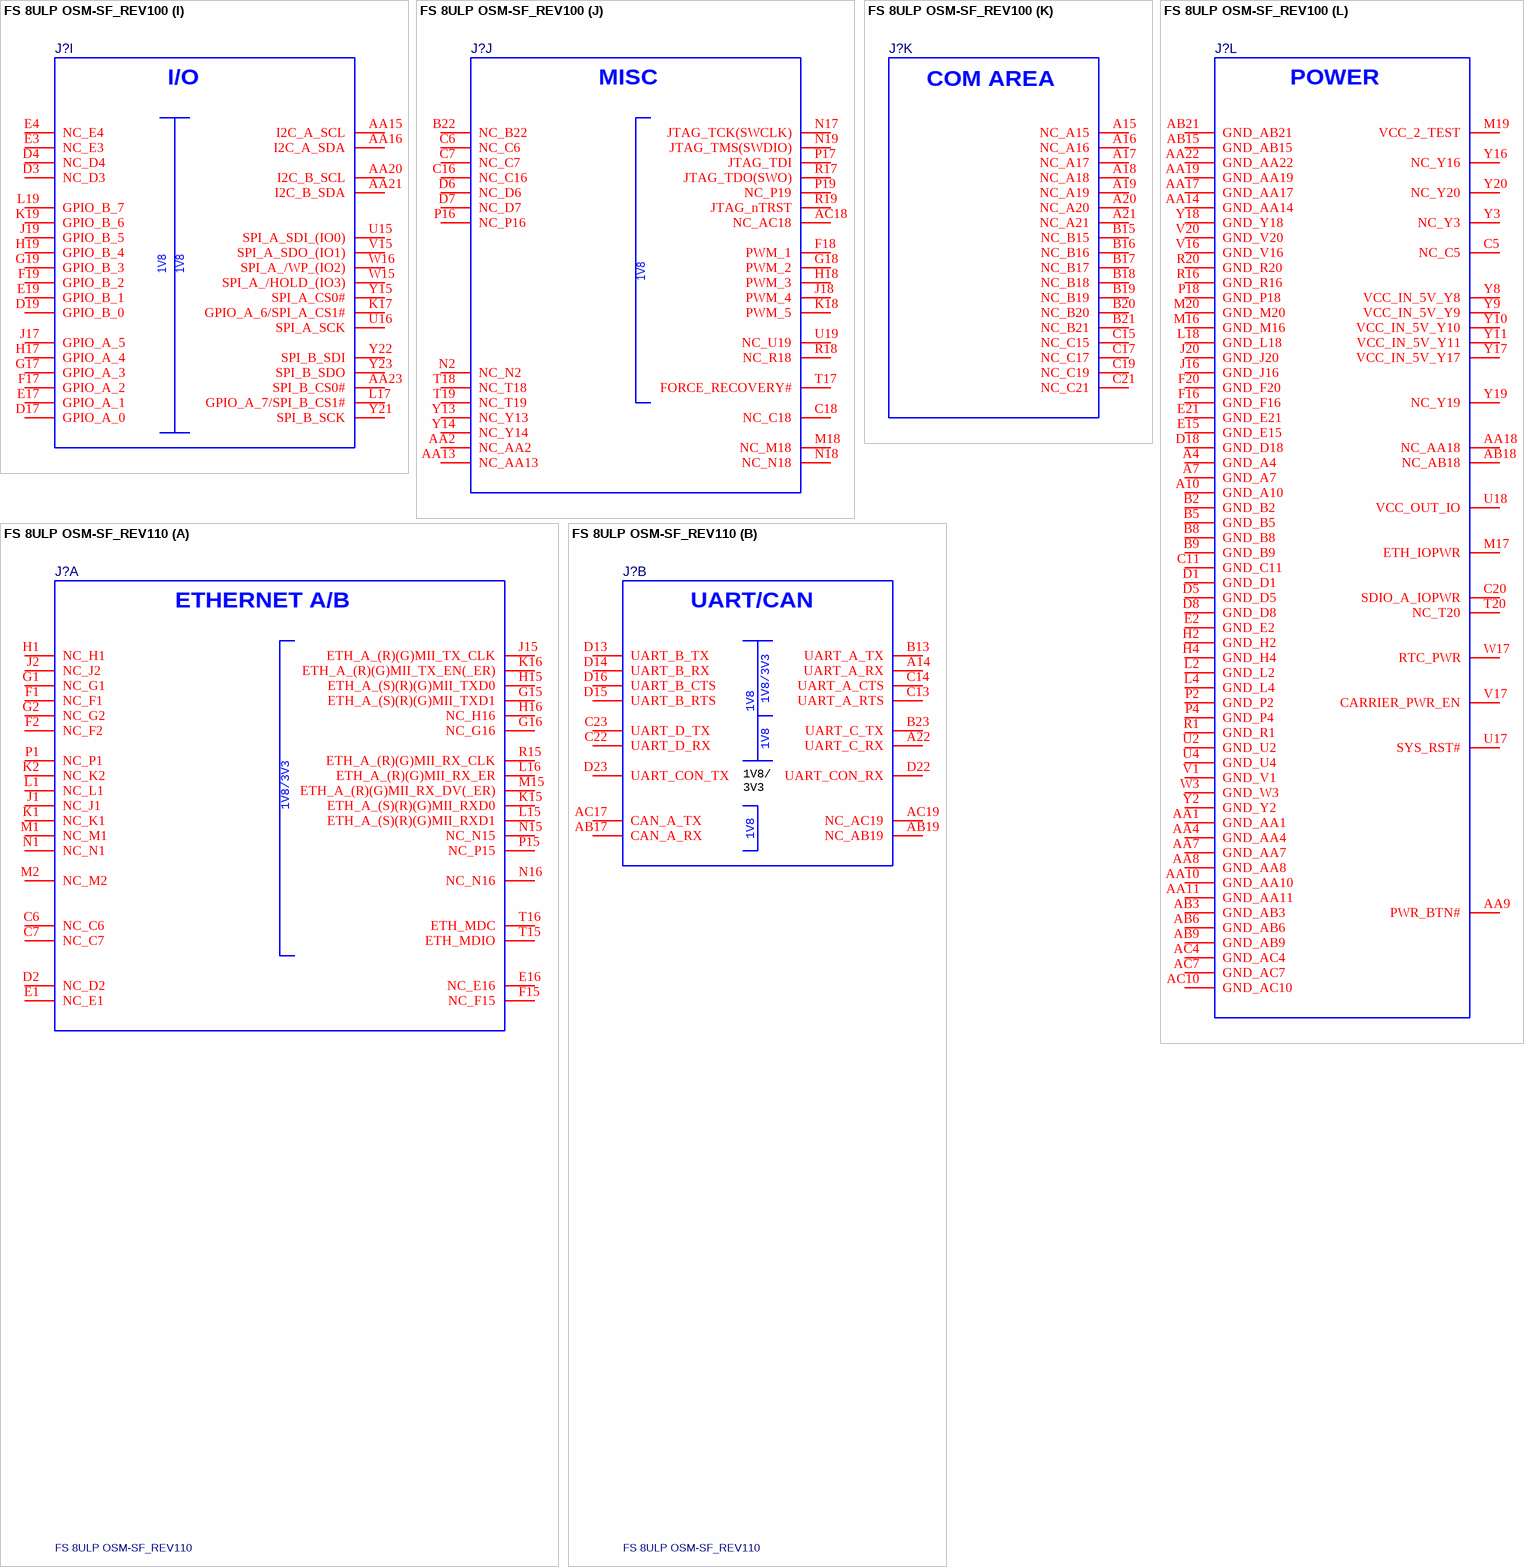
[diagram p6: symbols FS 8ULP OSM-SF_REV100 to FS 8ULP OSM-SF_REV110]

## FS 8ULP OSM-SF_REV100
designator J?  (value not drawn)
part A pins: D2 NC_D2, E1 NC_E1, E16 NC_E16, F1 NC_F1, F2 NC_F2, F15 NC_F15, G1 NC_G1, G2 NC_G2, G15 ETH_A_(S)(R)(G)MII_TXD1, G16 NC_G16, H1 NC_H1, H15 ETH_A_(S)(R)(G)MII_TXD0, H16 NC_H16, J1 NC_J1, J2 NC_J2, J15 ETH_A_(R)(G)MII_TX_CLK, K1 NC_K1, K2 NC_K2, K15 ETH_A_(S)(R)(G)MII_RXD0, K16 ETH_A_(R)(G)MII_TX_EN(_ER), L1 NC_L1, L15 ETH_A_(S)(R)(G)MII_RXD1, L16 ETH_A_(R)(G)MII_RX_ER, M1 NC_M1, M2 NC_M2, M15 ETH_A_(R)(G)MII_RX_DV(_ER), N1 NC_N1, N15 NC_N15, N16 NC_N16, P1 NC_P1, P15 NC_P15, R15 ETH_A_(R)(G)MII_RX_CLK, T15 ETH_MDIO, T16 ETH_MDC
part B pins: A14 UART_A_RX, A22 UART_C_RX, AB17 CAN_A_RX, AB19 NC_AB19, AC17 CAN_A_TX, AC19 NC_AC19, B13 UART_A_TX, B23 UART_C_TX, C13 UART_A_RTS, C14 UART_A_CTS, C22 UART_D_RX, C23 UART_D_TX, D13 UART_B_TX, D14 UART_B_RX, D15 UART_B_RTS, D16 UART_B_CTS, D22 UART_CON_RX, D23 UART_CON_TX
part C pins: D20 SDIO_A_WP, D21 SDIO_A_PWR_EN, E20 SDIO_A_CMD, F21 SDIO_A_CLK, G20 SDIO_A_D0, G21 SDIO_A_D1, H20 SDIO_A_D2, H21 SDIO_A_D3, J21 SDIO_A_CD#, K20 NC_K20, K21 NC_K21, L20 NC_L20, L21 NC_L21, M21 NC_M21, N20 NC_N20, N21 NC_N21, P20 NC_P20, P21 NC_P21, R21 NC_R21, T21 NC_T21, U20 NC_U20, U21 NC_U21
part D pins: AB1 NC_AB1, AB2 NC_AB2, AC2 NC_AC2, AC3 NC_AC3, R2 NC_R2, T1 NC_T1, T2 NC_T2, U1 NC_U1, V2 NC_V2, W1 NC_W1, W2 NC_W2, Y1 NC_Y1
part E pins: A2 CSI_DATA1_N, A3 CSI_DATA1_P, A5 NC_A5, A6 NC_A6, AA3 DSI_TE, AB4 DSI_DATA3_P, AB5 DSI_DATA3_N, AB7 DSI_CLOCK_P, AB8 DSI_CLOCK_N, AB10 DSI_DATA0_P, AB11 DSI_DATA0_N, AC5 DSI_DATA2_P, AC6 DSI_DATA2_N, AC8 DSI_DATA1_P, AC9 DSI_DATA1_N, B1 CSI_DATA0_P, B3 CSI_CLOCK_N, B4 CSI_CLOCK_P, B6 NC_B6, B7 NC_B7, C1 CSI_DATA0_N, C2 CAM_MCK, C3 I2C_CAM_SDA/CSI_TX_N, C4 I2C_CAM_SCL/CSI_TX_P, E18 PWM_0/DISP_BL_PWM, F3 GPIO_C_4/DISP_VDD_EN, F4 GPIO_C_5/DISP_BL_EN, G3 CAM_PWR/GPIO_C_6, G4 CAM_RST#/GPIO_C_7
part F pins: AA5 RGB_R3, AA6 RGB_R1, H3 RGB_CS#, J3 RGB_RESET#, J4 RGB_DE, K3 RGB_HSYNC, K4 RGB_DISP, L3 RGB_VSYNC, M3 RGB_B5, M4 RGB_CLK, N3 RGB_B3, N4 RGB_B4, P3 RGB_B2, R3 RGB_B1, R4 RGB_B0, T3 RGB_G4, T4 RGB_G5, U3 RGB_G3, V3 RGB_G1, V4 RGB_G2, W4 RGB_G0, Y4 RGB_R5, Y5 RGB_R4, Y6 RGB_R2, Y7 RGB_R0
part G pins: A8 NC_A8, A9 NC_A9, AB13 USB_A_D_N, AB14 USB_A_ID, AB16 USB_A_VBUS, AB20 USB_B_VBUS, AB22 USB_B_ID, AB23 USB_B_D_N, AC14 USB_A_D_P, AC15 USB_A_OC#, AC16 USB_A_EN, AC20 USB_B_EN, AC21 USB_B_OC#, AC22 USB_B_D_P, B10 NC_B10, B11 NC_B11, C8 NC_C8, C9 NC_C9, C10 NC_C10, D9 NC_D9, D10 NC_D10, D11 NC_D11
part H pins: V18 I2S_MCLK, V19 I2S_B_DATA_IN, V21 I2S_A_DATA_IN, W18 I2S_LRCLK, W19 I2S_B_DATA_OUT, W20 I2S_BITCLK, W21 I2S_A_DATA_OUT
part I pins: AA15 I2C_A_SCL, AA16 I2C_A_SDA, AA20 I2C_B_SCL, AA21 I2C_B_SDA, AA23 SPI_B_CS0#, D3 NC_D3, D4 NC_D4, D17 GPIO_A_0, D19 GPIO_B_0, E3 NC_E3, E4 NC_E4, E17 GPIO_A_1, E19 GPIO_B_1, F17 GPIO_A_2, F19 GPIO_B_2, G17 GPIO_A_3, G19 GPIO_B_3, H17 GPIO_A_4, H19 GPIO_B_4, J17 GPIO_A_5, J19 GPIO_B_5, K17 GPIO_A_6/SPI_A_CS1#, K19 GPIO_B_6, L17 GPIO_A_7/SPI_B_CS1#, L19 GPIO_B_7, U15 SPI_A_SDI_(IO0), U16 SPI_A_SCK, V15 SPI_A_SDO_(IO1), W15 SPI_A_/HOLD_(IO3), W16 SPI_A_/WP_(IO2), Y15 SPI_A_CS0#, Y21 SPI_B_SCK, Y22 SPI_B_SDI, Y23 SPI_B_SDO
part J pins: AA2 NC_AA2, AA13 NC_AA13, AC18 NC_AC18, B22 NC_B22, C6 NC_C6, C7 NC_C7, C16 NC_C16, C18 NC_C18, D6 NC_D6, D7 NC_D7, F18 PWM_1, G18 PWM_2, H18 PWM_3, J18 PWM_4, K18 PWM_5, M18 NC_M18, N2 NC_N2, N17 JTAG_TCK(SWCLK), N18 NC_N18, N19 JTAG_TMS(SWDIO), P16 NC_P16, P17 JTAG_TDI, P19 NC_P19, R17 JTAG_TDO(SWO), R18 NC_R18, R19 JTAG_nTRST, T17 FORCE_RECOVERY#, T18 NC_T18, T19 NC_T19, U19 NC_U19, Y13 NC_Y13, Y14 NC_Y14
part K pins: A15 NC_A15, A16 NC_A16, A17 NC_A17, A18 NC_A18, A19 NC_A19, A20 NC_A20, A21 NC_A21, B15 NC_B15, B16 NC_B16, B17 NC_B17, B18 NC_B18, B19 NC_B19, B20 NC_B20, B21 NC_B21, C15 NC_C15, C17 NC_C17, C19 NC_C19, C21 NC_C21
part L pins: A4 GND_A4 (power), A7 GND_A7 (power), A10 GND_A10 (power), AA1 GND_AA1 (power), AA4 GND_AA4 (power), AA7 GND_AA7 (power), AA8 GND_AA8 (power), AA9 PWR_BTN#, AA10 GND_AA10 (power), AA11 GND_AA11 (power), AA14 GND_AA14 (power), AA17 GND_AA17 (power), AA18 NC_AA18, AA19 GND_AA19 (power), AA22 GND_AA22 (power), AB3 GND_AB3 (power), AB6 GND_AB6 (power), AB9 GND_AB9 (power), AB15 GND_AB15 (power), AB18 NC_AB18, AB21 GND_AB21 (power), AC4 GND_AC4 (power), AC7 GND_AC7 (power), AC10 GND_AC10 (power), B2 GND_B2 (power), B5 GND_B5 (power), B8 GND_B8 (power), B9 GND_B9 (power), C5 NC_C5, C11 GND_C11 (power), C20 SDIO_A_IOPWR, D1 GND_D1 (power), D5 GND_D5 (power), D8 GND_D8 (power), D18 GND_D18 (power), E2 GND_E2 (power), E15 GND_E15 (power), E21 GND_E21 (power), F16 GND_F16 (power), F20 GND_F20 (power), H2 GND_H2 (power), H4 GND_H4 (power), J16 GND_J16 (power), J20 GND_J20 (power), L2 GND_L2 (power), L4 GND_L4 (power), L18 GND_L18 (power), M16 GND_M16 (power), M17 ETH_IOPWR (power), M19 VCC_2_TEST, M20 GND_M20 (power), P2 GND_P2 (power), P4 GND_P4 (power), P18 GND_P18 (power), R1 GND_R1 (power), R16 GND_R16 (power), R20 GND_R20 (power), T20 NC_T20, U2 GND_U2 (power), U4 GND_U4 (power), U17 SYS_RST#, U18 VCC_OUT_IO, V1 GND_V1 (power), V16 GND_V16 (power), V17 CARRIER_PWR_EN, V20 GND_V20 (power), W3 GND_W3 (power), W17 RTC_PWR (power), Y2 GND_Y2 (power), Y3 NC_Y3, Y8 VCC_IN_5V_Y8 (power), Y9 VCC_IN_5V_Y9 (power), Y10 VCC_IN_5V_Y10 (power), Y11 VCC_IN_5V_Y11 (power), Y16 NC_Y16, Y17 VCC_IN_5V_Y17 (power), Y18 GND_Y18 (power), Y19 NC_Y19, Y20 NC_Y20

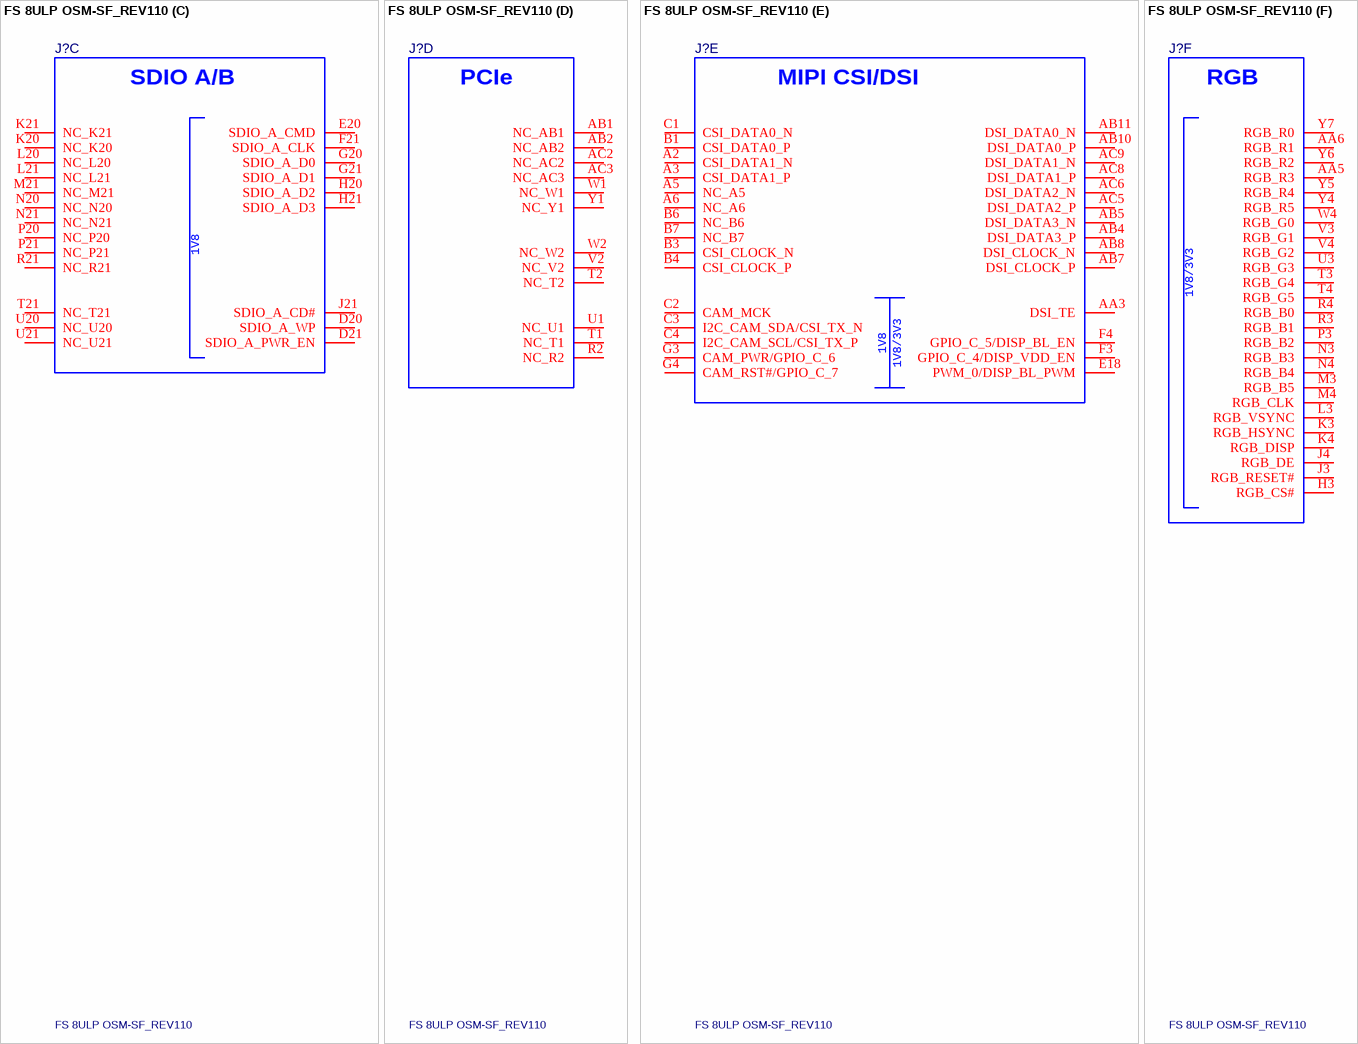
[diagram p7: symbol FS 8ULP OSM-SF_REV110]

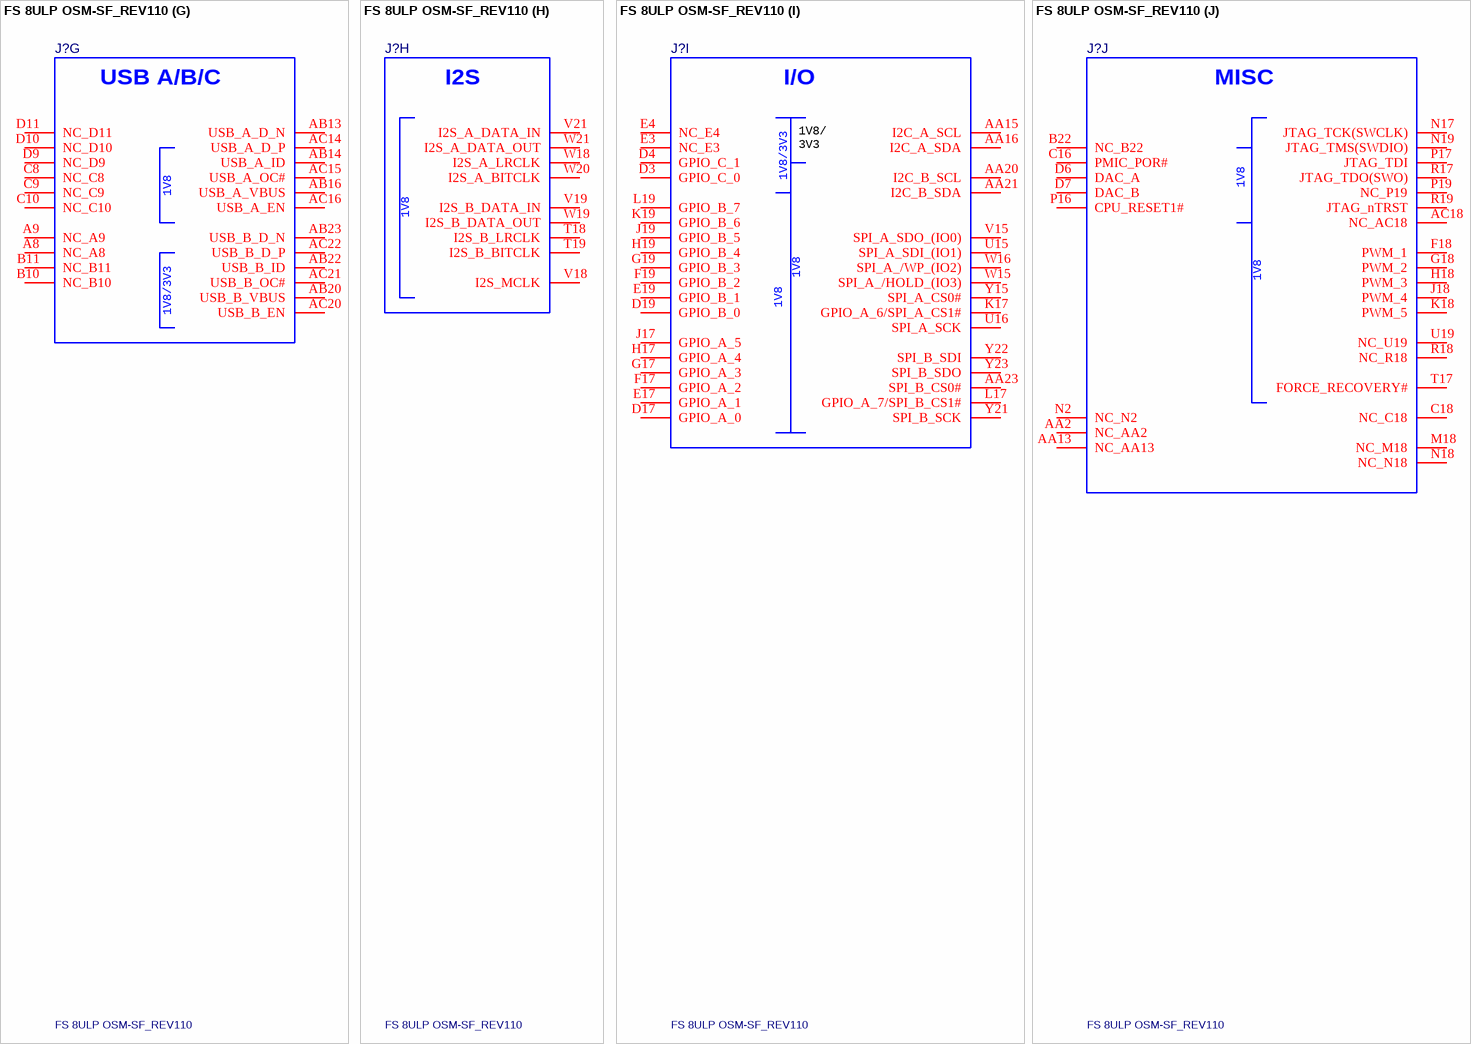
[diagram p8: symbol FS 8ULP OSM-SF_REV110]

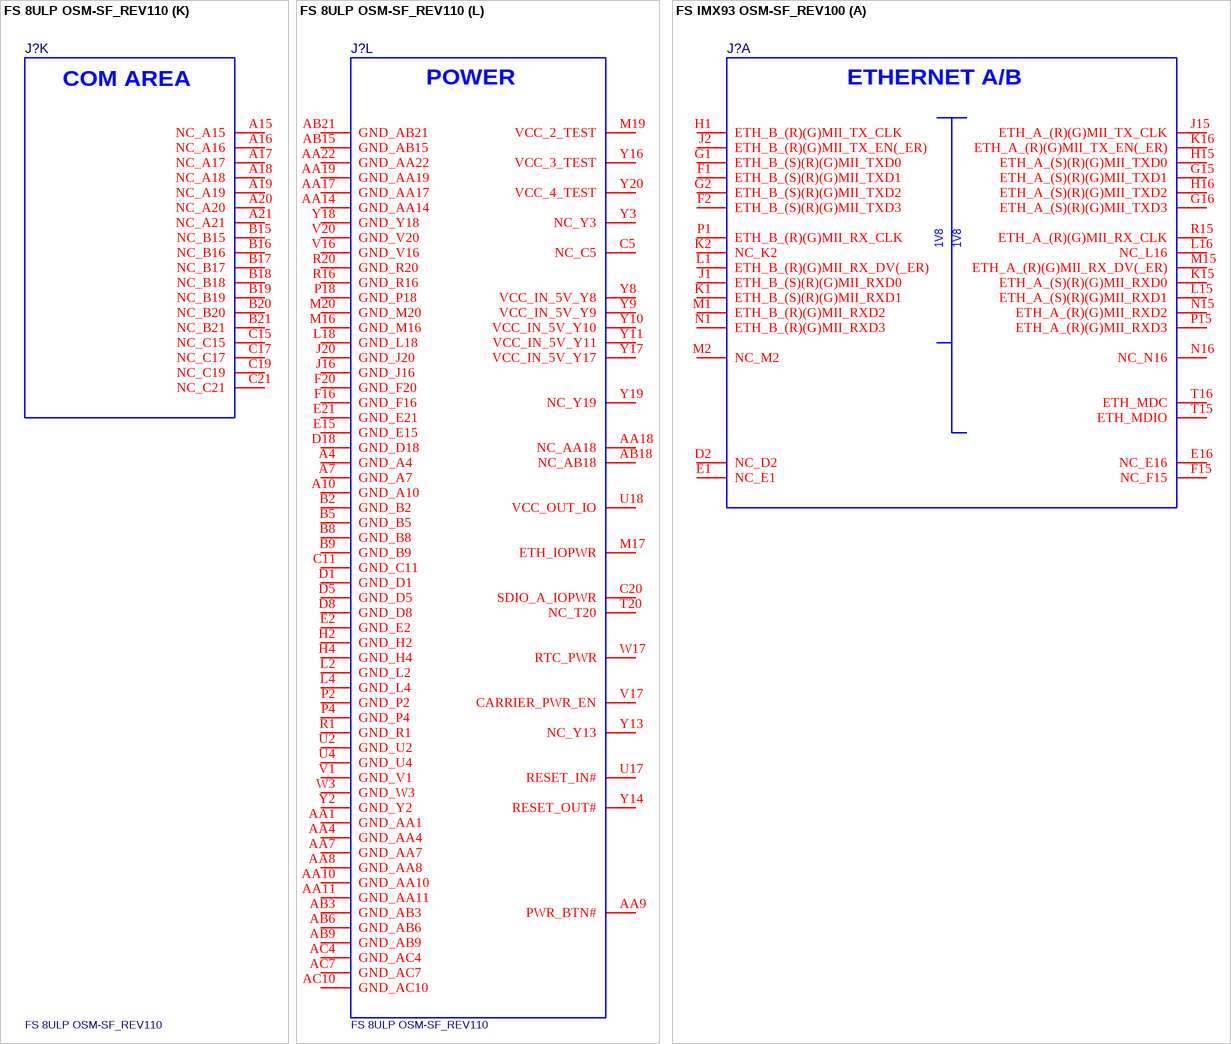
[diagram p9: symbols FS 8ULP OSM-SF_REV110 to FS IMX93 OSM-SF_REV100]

## FS 8ULP OSM-SF_REV110
designator J?
part A pins: C6 NC_C6, C7 NC_C7, D2 NC_D2, E1 NC_E1, E16 NC_E16, F1 NC_F1, F2 NC_F2, F15 NC_F15, G1 NC_G1, G2 NC_G2, G15 ETH_A_(S)(R)(G)MII_TXD1, G16 NC_G16, H1 NC_H1, H15 ETH_A_(S)(R)(G)MII_TXD0, H16 NC_H16, J1 NC_J1, J2 NC_J2, J15 ETH_A_(R)(G)MII_TX_CLK, K1 NC_K1, K2 NC_K2, K15 ETH_A_(S)(R)(G)MII_RXD0, K16 ETH_A_(R)(G)MII_TX_EN(_ER), L1 NC_L1, L15 ETH_A_(S)(R)(G)MII_RXD1, L16 ETH_A_(R)(G)MII_RX_ER, M1 NC_M1, M2 NC_M2, M15 ETH_A_(R)(G)MII_RX_DV(_ER), N1 NC_N1, N15 NC_N15, N16 NC_N16, P1 NC_P1, P15 NC_P15, R15 ETH_A_(R)(G)MII_RX_CLK, T15 ETH_MDIO, T16 ETH_MDC
part B pins: A14 UART_A_RX, A22 UART_C_RX, AB17 CAN_A_RX, AB19 NC_AB19, AC17 CAN_A_TX, AC19 NC_AC19, B13 UART_A_TX, B23 UART_C_TX, C13 UART_A_RTS, C14 UART_A_CTS, C22 UART_D_RX, C23 UART_D_TX, D13 UART_B_TX, D14 UART_B_RX, D15 UART_B_RTS, D16 UART_B_CTS, D22 UART_CON_RX, D23 UART_CON_TX
part C pins: D20 SDIO_A_WP, D21 SDIO_A_PWR_EN, E20 SDIO_A_CMD, F21 SDIO_A_CLK, G20 SDIO_A_D0, G21 SDIO_A_D1, H20 SDIO_A_D2, H21 SDIO_A_D3, J21 SDIO_A_CD#, K20 NC_K20, K21 NC_K21, L20 NC_L20, L21 NC_L21, M21 NC_M21, N20 NC_N20, N21 NC_N21, P20 NC_P20, P21 NC_P21, R21 NC_R21, T21 NC_T21, U20 NC_U20, U21 NC_U21
part D pins: AB1 NC_AB1, AB2 NC_AB2, AC2 NC_AC2, AC3 NC_AC3, R2 NC_R2, T1 NC_T1, T2 NC_T2, U1 NC_U1, V2 NC_V2, W1 NC_W1, W2 NC_W2, Y1 NC_Y1
part E pins: A2 CSI_DATA1_N, A3 CSI_DATA1_P, A5 NC_A5, A6 NC_A6, AA3 DSI_TE, AB4 DSI_DATA3_P, AB5 DSI_DATA3_N, AB7 DSI_CLOCK_P, AB8 DSI_CLOCK_N, AB10 DSI_DATA0_P, AB11 DSI_DATA0_N, AC5 DSI_DATA2_P, AC6 DSI_DATA2_N, AC8 DSI_DATA1_P, AC9 DSI_DATA1_N, B1 CSI_DATA0_P, B3 CSI_CLOCK_N, B4 CSI_CLOCK_P, B6 NC_B6, B7 NC_B7, C1 CSI_DATA0_N, C2 CAM_MCK, C3 I2C_CAM_SDA/CSI_TX_N, C4 I2C_CAM_SCL/CSI_TX_P, E18 PWM_0/DISP_BL_PWM, F3 GPIO_C_4/DISP_VDD_EN, F4 GPIO_C_5/DISP_BL_EN, G3 CAM_PWR/GPIO_C_6, G4 CAM_RST#/GPIO_C_7
part F pins: AA5 RGB_R3, AA6 RGB_R1, H3 RGB_CS#, J3 RGB_RESET#, J4 RGB_DE, K3 RGB_HSYNC, K4 RGB_DISP, L3 RGB_VSYNC, M3 RGB_B5, M4 RGB_CLK, N3 RGB_B3, N4 RGB_B4, P3 RGB_B2, R3 RGB_B1, R4 RGB_B0, T3 RGB_G4, T4 RGB_G5, U3 RGB_G3, V3 RGB_G1, V4 RGB_G2, W4 RGB_G0, Y4 RGB_R5, Y5 RGB_R4, Y6 RGB_R2, Y7 RGB_R0
part G pins: A8 NC_A8, A9 NC_A9, AB13 USB_A_D_N, AB14 USB_A_ID, AB16 USB_A_VBUS, AB20 USB_B_VBUS, AB22 USB_B_ID, AB23 USB_B_D_N, AC14 USB_A_D_P, AC15 USB_A_OC#, AC16 USB_A_EN, AC20 USB_B_EN, AC21 USB_B_OC#, AC22 USB_B_D_P, B10 NC_B10, B11 NC_B11, C8 NC_C8, C9 NC_C9, C10 NC_C10, D9 NC_D9, D10 NC_D10, D11 NC_D11
part H pins: T18 I2S_B_LRCLK, T19 I2S_B_BITCLK, V18 I2S_MCLK, V19 I2S_B_DATA_IN, V21 I2S_A_DATA_IN, W18 I2S_A_LRCLK, W19 I2S_B_DATA_OUT, W20 I2S_A_BITCLK, W21 I2S_A_DATA_OUT
part I pins: AA15 I2C_A_SCL, AA16 I2C_A_SDA, AA20 I2C_B_SCL, AA21 I2C_B_SDA, AA23 SPI_B_CS0#, D3 GPIO_C_0, D4 GPIO_C_1, D17 GPIO_A_0, D19 GPIO_B_0, E3 NC_E3, E4 NC_E4, E17 GPIO_A_1, E19 GPIO_B_1, F17 GPIO_A_2, F19 GPIO_B_2, G17 GPIO_A_3, G19 GPIO_B_3, H17 GPIO_A_4, H19 GPIO_B_4, J17 GPIO_A_5, J19 GPIO_B_5, K17 GPIO_A_6/SPI_A_CS1#, K19 GPIO_B_6, L17 GPIO_A_7/SPI_B_CS1#, L19 GPIO_B_7, U15 SPI_A_SDI_(IO1), U16 SPI_A_SCK, V15 SPI_A_SDO_(IO0), W15 SPI_A_/HOLD_(IO3), W16 SPI_A_/WP_(IO2), Y15 SPI_A_CS0#, Y21 SPI_B_SCK, Y22 SPI_B_SDI, Y23 SPI_B_SDO
part J pins: AA2 NC_AA2, AA13 NC_AA13, AC18 NC_AC18, B22 NC_B22, C16 PMIC_POR#, C18 NC_C18, D6 DAC_A, D7 DAC_B, F18 PWM_1, G18 PWM_2, H18 PWM_3, J18 PWM_4, K18 PWM_5, M18 NC_M18, N2 NC_N2, N17 JTAG_TCK(SWCLK), N18 NC_N18, N19 JTAG_TMS(SWDIO), P16 CPU_RESET1#, P17 JTAG_TDI, P19 NC_P19, R17 JTAG_TDO(SWO), R18 NC_R18, R19 JTAG_nTRST, T17 FORCE_RECOVERY#, U19 NC_U19
part K pins: A15 NC_A15, A16 NC_A16, A17 NC_A17, A18 NC_A18, A19 NC_A19, A20 NC_A20, A21 NC_A21, B15 NC_B15, B16 NC_B16, B17 NC_B17, B18 NC_B18, B19 NC_B19, B20 NC_B20, B21 NC_B21, C15 NC_C15, C17 NC_C17, C19 NC_C19, C21 NC_C21
part L pins: A4 GND_A4 (power), A7 GND_A7 (power), A10 GND_A10 (power), AA1 GND_AA1 (power), AA4 GND_AA4 (power), AA7 GND_AA7 (power), AA8 GND_AA8 (power), AA9 PWR_BTN#, AA10 GND_AA10 (power), AA11 GND_AA11 (power), AA14 GND_AA14 (power), AA17 GND_AA17 (power), AA18 NC_AA18, AA19 GND_AA19 (power), AA22 GND_AA22 (power), AB3 GND_AB3 (power), AB6 GND_AB6 (power), AB9 GND_AB9 (power), AB15 GND_AB15 (power), AB18 NC_AB18, AB21 GND_AB21 (power), AC4 GND_AC4 (power), AC7 GND_AC7 (power), AC10 GND_AC10 (power), B2 GND_B2 (power), B5 GND_B5 (power), B8 GND_B8 (power), B9 GND_B9 (power), C5 NC_C5, C11 GND_C11 (power), C20 SDIO_A_IOPWR, D1 GND_D1 (power), D5 GND_D5 (power), D8 GND_D8 (power), D18 GND_D18 (power), E2 GND_E2 (power), E15 GND_E15 (power), E21 GND_E21 (power), F16 GND_F16 (power), F20 GND_F20 (power), H2 GND_H2 (power), H4 GND_H4 (power), J16 GND_J16 (power), J20 GND_J20 (power), L2 GND_L2 (power), L4 GND_L4 (power), L18 GND_L18 (power), M16 GND_M16 (power), M17 ETH_IOPWR (power), M19 VCC_2_TEST, M20 GND_M20 (power), P2 GND_P2 (power), P4 GND_P4 (power), P18 GND_P18 (power), R1 GND_R1 (power), R16 GND_R16 (power), R20 GND_R20 (power), T20 NC_T20, U2 GND_U2 (power), U4 GND_U4 (power), U17 RESET_IN#, U18 VCC_OUT_IO, V1 GND_V1 (power), V16 GND_V16 (power), V17 CARRIER_PWR_EN, V20 GND_V20 (power), W3 GND_W3 (power), W17 RTC_PWR (power), Y2 GND_Y2 (power), Y3 NC_Y3, Y8 VCC_IN_5V_Y8 (power), Y9 VCC_IN_5V_Y9 (power), Y10 VCC_IN_5V_Y10 (power), Y11 VCC_IN_5V_Y11 (power), Y13 NC_Y13, Y14 RESET_OUT#, Y16 VCC_3_TEST, Y17 VCC_IN_5V_Y17 (power), Y18 GND_Y18 (power), Y19 NC_Y19, Y20 VCC_4_TEST

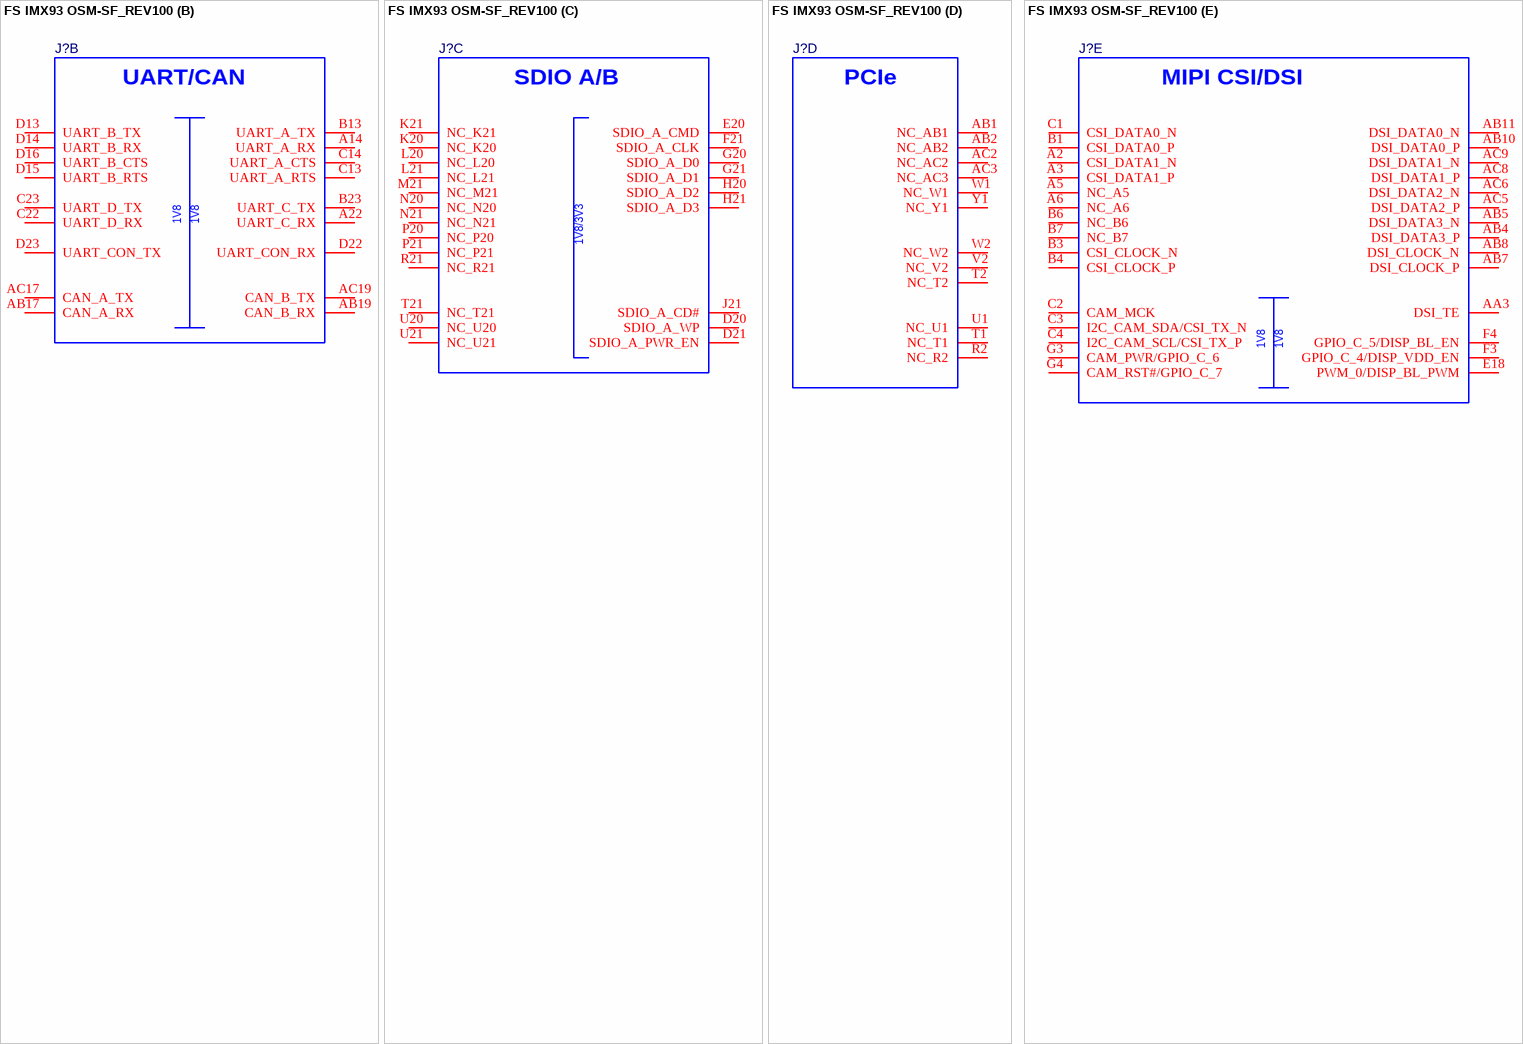
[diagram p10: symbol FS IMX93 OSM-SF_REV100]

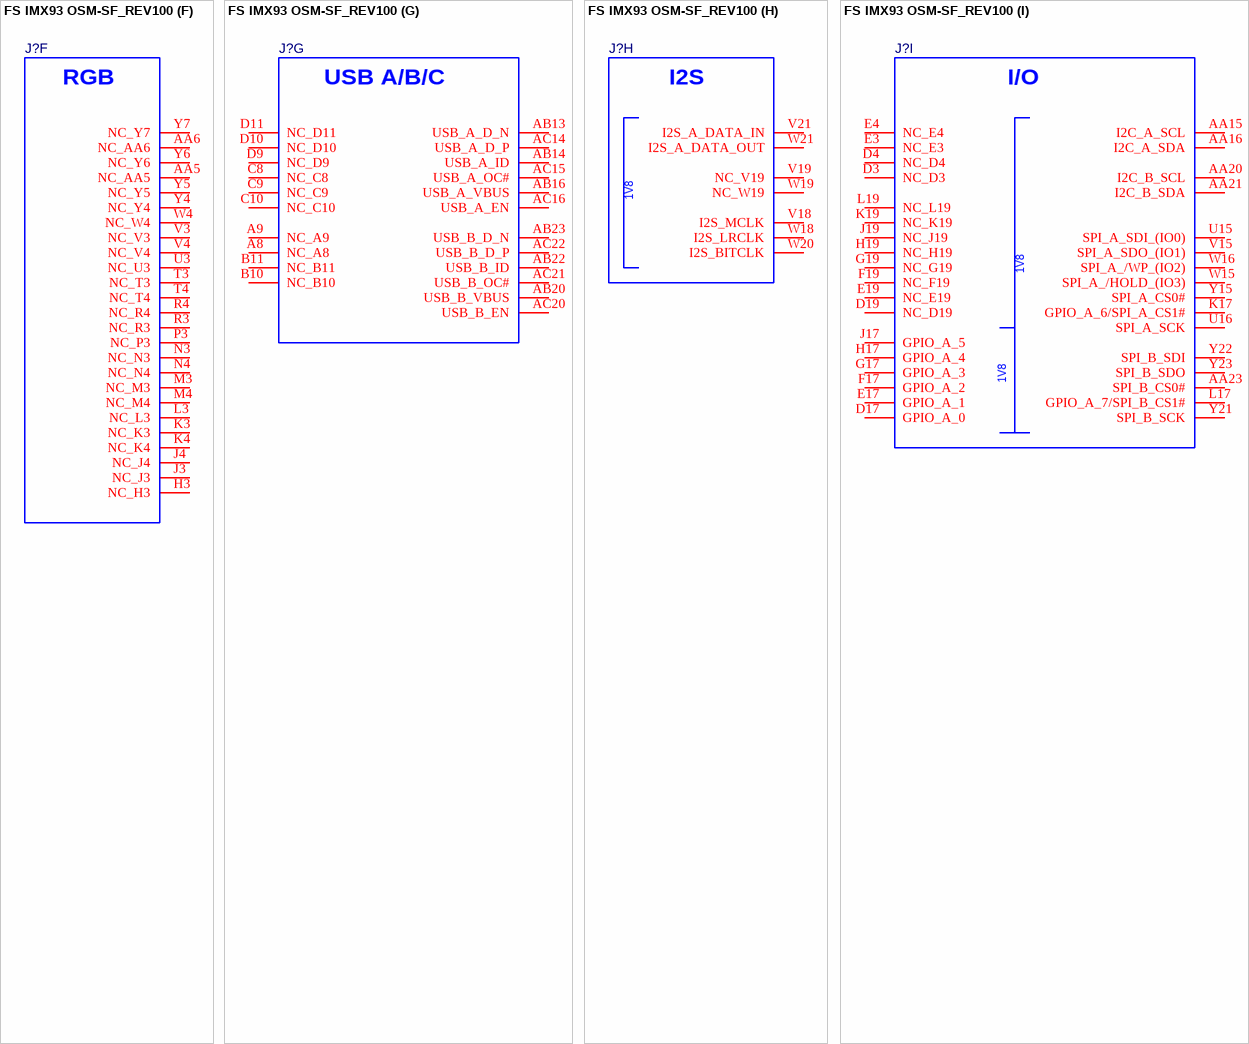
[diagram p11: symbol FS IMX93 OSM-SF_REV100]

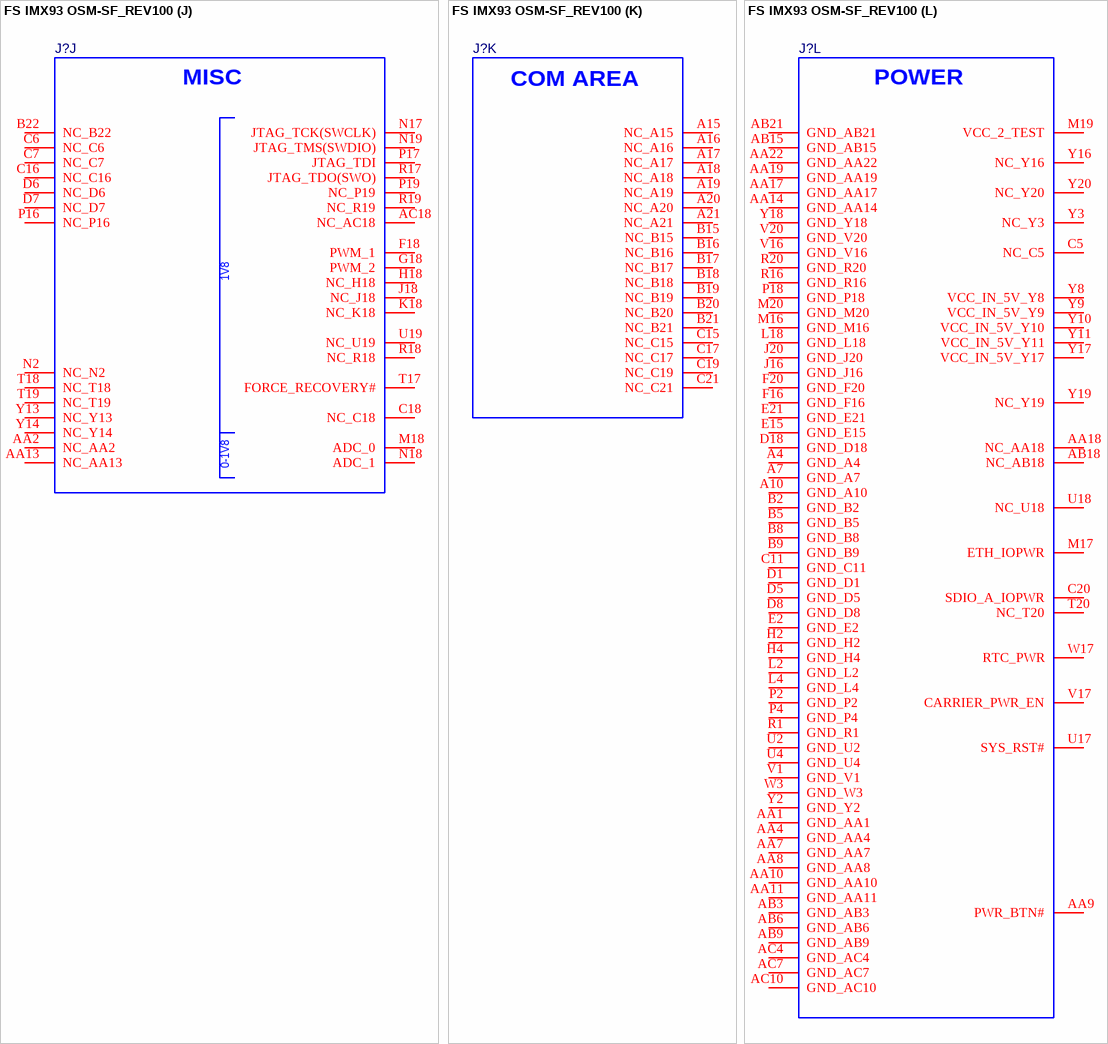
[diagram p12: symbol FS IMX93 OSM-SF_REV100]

## FS IMX93 OSM-SF_REV100
designator J?  (value not drawn)
part A pins: D2 NC_D2, E1 NC_E1, E16 NC_E16, F1 ETH_B_(S)(R)(G)MII_TXD1, F2 ETH_B_(S)(R)(G)MII_TXD3, F15 NC_F15, G1 ETH_B_(S)(R)(G)MII_TXD0, G2 ETH_B_(S)(R)(G)MII_TXD2, G15 ETH_A_(S)(R)(G)MII_TXD1, G16 ETH_A_(S)(R)(G)MII_TXD3, H1 ETH_B_(R)(G)MII_TX_CLK, H15 ETH_A_(S)(R)(G)MII_TXD0, H16 ETH_A_(S)(R)(G)MII_TXD2, J1 ETH_B_(S)(R)(G)MII_RXD0, J2 ETH_B_(R)(G)MII_TX_EN(_ER), J15 ETH_A_(R)(G)MII_TX_CLK, K1 ETH_B_(S)(R)(G)MII_RXD1, K2 NC_K2, K15 ETH_A_(S)(R)(G)MII_RXD0, K16 ETH_A_(R)(G)MII_TX_EN(_ER), L1 ETH_B_(R)(G)MII_RX_DV(_ER), L15 ETH_A_(S)(R)(G)MII_RXD1, L16 NC_L16, M1 ETH_B_(R)(G)MII_RXD2, M2 NC_M2, M15 ETH_A_(R)(G)MII_RX_DV(_ER), N1 ETH_B_(R)(G)MII_RXD3, N15 ETH_A_(R)(G)MII_RXD2, N16 NC_N16, P1 ETH_B_(R)(G)MII_RX_CLK, P15 ETH_A_(R)(G)MII_RXD3, R15 ETH_A_(R)(G)MII_RX_CLK, T15 ETH_MDIO, T16 ETH_MDC
part B pins: A14 UART_A_RX, A22 UART_C_RX, AB17 CAN_A_RX, AB19 CAN_B_RX, AC17 CAN_A_TX, AC19 CAN_B_TX, B13 UART_A_TX, B23 UART_C_TX, C13 UART_A_RTS, C14 UART_A_CTS, C22 UART_D_RX, C23 UART_D_TX, D13 UART_B_TX, D14 UART_B_RX, D15 UART_B_RTS, D16 UART_B_CTS, D22 UART_CON_RX, D23 UART_CON_TX
part C pins: D20 SDIO_A_WP, D21 SDIO_A_PWR_EN, E20 SDIO_A_CMD, F21 SDIO_A_CLK, G20 SDIO_A_D0, G21 SDIO_A_D1, H20 SDIO_A_D2, H21 SDIO_A_D3, J21 SDIO_A_CD#, K20 NC_K20, K21 NC_K21, L20 NC_L20, L21 NC_L21, M21 NC_M21, N20 NC_N20, N21 NC_N21, P20 NC_P20, P21 NC_P21, R21 NC_R21, T21 NC_T21, U20 NC_U20, U21 NC_U21
part D pins: AB1 NC_AB1, AB2 NC_AB2, AC2 NC_AC2, AC3 NC_AC3, R2 NC_R2, T1 NC_T1, T2 NC_T2, U1 NC_U1, V2 NC_V2, W1 NC_W1, W2 NC_W2, Y1 NC_Y1
part E pins: A2 CSI_DATA1_N, A3 CSI_DATA1_P, A5 NC_A5, A6 NC_A6, AA3 DSI_TE, AB4 DSI_DATA3_P, AB5 DSI_DATA3_N, AB7 DSI_CLOCK_P, AB8 DSI_CLOCK_N, AB10 DSI_DATA0_P, AB11 DSI_DATA0_N, AC5 DSI_DATA2_P, AC6 DSI_DATA2_N, AC8 DSI_DATA1_P, AC9 DSI_DATA1_N, B1 CSI_DATA0_P, B3 CSI_CLOCK_N, B4 CSI_CLOCK_P, B6 NC_B6, B7 NC_B7, C1 CSI_DATA0_N, C2 CAM_MCK, C3 I2C_CAM_SDA/CSI_TX_N, C4 I2C_CAM_SCL/CSI_TX_P, E18 PWM_0/DISP_BL_PWM, F3 GPIO_C_4/DISP_VDD_EN, F4 GPIO_C_5/DISP_BL_EN, G3 CAM_PWR/GPIO_C_6, G4 CAM_RST#/GPIO_C_7
part F pins: AA5 NC_AA5, AA6 NC_AA6, H3 NC_H3, J3 NC_J3, J4 NC_J4, K3 NC_K3, K4 NC_K4, L3 NC_L3, M3 NC_M3, M4 NC_M4, N3 NC_N3, N4 NC_N4, P3 NC_P3, R3 NC_R3, R4 NC_R4, T3 NC_T3, T4 NC_T4, U3 NC_U3, V3 NC_V3, V4 NC_V4, W4 NC_W4, Y4 NC_Y4, Y5 NC_Y5, Y6 NC_Y6, Y7 NC_Y7
part G pins: A8 NC_A8, A9 NC_A9, AB13 USB_A_D_N, AB14 USB_A_ID, AB16 USB_A_VBUS, AB20 USB_B_VBUS, AB22 USB_B_ID, AB23 USB_B_D_N, AC14 USB_A_D_P, AC15 USB_A_OC#, AC16 USB_A_EN, AC20 USB_B_EN, AC21 USB_B_OC#, AC22 USB_B_D_P, B10 NC_B10, B11 NC_B11, C8 NC_C8, C9 NC_C9, C10 NC_C10, D9 NC_D9, D10 NC_D10, D11 NC_D11
part H pins: V18 I2S_MCLK, V19 NC_V19, V21 I2S_A_DATA_IN, W18 I2S_LRCLK, W19 NC_W19, W20 I2S_BITCLK, W21 I2S_A_DATA_OUT
part I pins: AA15 I2C_A_SCL, AA16 I2C_A_SDA, AA20 I2C_B_SCL, AA21 I2C_B_SDA, AA23 SPI_B_CS0#, D3 NC_D3, D4 NC_D4, D17 GPIO_A_0, D19 NC_D19, E3 NC_E3, E4 NC_E4, E17 GPIO_A_1, E19 NC_E19, F17 GPIO_A_2, F19 NC_F19, G17 GPIO_A_3, G19 NC_G19, H17 GPIO_A_4, H19 NC_H19, J17 GPIO_A_5, J19 NC_J19, K17 GPIO_A_6/SPI_A_CS1#, K19 NC_K19, L17 GPIO_A_7/SPI_B_CS1#, L19 NC_L19, U15 SPI_A_SDI_(IO0), U16 SPI_A_SCK, V15 SPI_A_SDO_(IO1), W15 SPI_A_/HOLD_(IO3), W16 SPI_A_/WP_(IO2), Y15 SPI_A_CS0#, Y21 SPI_B_SCK, Y22 SPI_B_SDI, Y23 SPI_B_SDO
part J pins: AA2 NC_AA2, AA13 NC_AA13, AC18 NC_AC18, B22 NC_B22, C6 NC_C6, C7 NC_C7, C16 NC_C16, C18 NC_C18, D6 NC_D6, D7 NC_D7, F18 PWM_1, G18 PWM_2, H18 NC_H18, J18 NC_J18, K18 NC_K18, M18 ADC_0, N2 NC_N2, N17 JTAG_TCK(SWCLK), N18 ADC_1, N19 JTAG_TMS(SWDIO), P16 NC_P16, P17 JTAG_TDI, P19 NC_P19, R17 JTAG_TDO(SWO), R18 NC_R18, R19 NC_R19, T17 FORCE_RECOVERY#, T18 NC_T18, T19 NC_T19, U19 NC_U19, Y13 NC_Y13, Y14 NC_Y14
part K pins: A15 NC_A15, A16 NC_A16, A17 NC_A17, A18 NC_A18, A19 NC_A19, A20 NC_A20, A21 NC_A21, B15 NC_B15, B16 NC_B16, B17 NC_B17, B18 NC_B18, B19 NC_B19, B20 NC_B20, B21 NC_B21, C15 NC_C15, C17 NC_C17, C19 NC_C19, C21 NC_C21
part L pins: A4 GND_A4 (power), A7 GND_A7 (power), A10 GND_A10 (power), AA1 GND_AA1 (power), AA4 GND_AA4 (power), AA7 GND_AA7 (power), AA8 GND_AA8 (power), AA9 PWR_BTN#, AA10 GND_AA10 (power), AA11 GND_AA11 (power), AA14 GND_AA14 (power), AA17 GND_AA17 (power), AA18 NC_AA18, AA19 GND_AA19 (power), AA22 GND_AA22 (power), AB3 GND_AB3 (power), AB6 GND_AB6 (power), AB9 GND_AB9 (power), AB15 GND_AB15 (power), AB18 NC_AB18, AB21 GND_AB21 (power), AC4 GND_AC4 (power), AC7 GND_AC7 (power), AC10 GND_AC10 (power), B2 GND_B2 (power), B5 GND_B5 (power), B8 GND_B8 (power), B9 GND_B9 (power), C5 NC_C5, C11 GND_C11 (power), C20 SDIO_A_IOPWR, D1 GND_D1 (power), D5 GND_D5 (power), D8 GND_D8 (power), D18 GND_D18 (power), E2 GND_E2 (power), E15 GND_E15 (power), E21 GND_E21 (power), F16 GND_F16 (power), F20 GND_F20 (power), H2 GND_H2 (power), H4 GND_H4 (power), J16 GND_J16 (power), J20 GND_J20 (power), L2 GND_L2 (power), L4 GND_L4 (power), L18 GND_L18 (power), M16 GND_M16 (power), M17 ETH_IOPWR (power), M19 VCC_2_TEST, M20 GND_M20 (power), P2 GND_P2 (power), P4 GND_P4 (power), P18 GND_P18 (power), R1 GND_R1 (power), R16 GND_R16 (power), R20 GND_R20 (power), T20 NC_T20, U2 GND_U2 (power), U4 GND_U4 (power), U17 SYS_RST#, U18 NC_U18, V1 GND_V1 (power), V16 GND_V16 (power), V17 CARRIER_PWR_EN, V20 GND_V20 (power), W3 GND_W3 (power), W17 RTC_PWR (power), Y2 GND_Y2 (power), Y3 NC_Y3, Y8 VCC_IN_5V_Y8 (power), Y9 VCC_IN_5V_Y9 (power), Y10 VCC_IN_5V_Y10 (power), Y11 VCC_IN_5V_Y11 (power), Y16 NC_Y16, Y17 VCC_IN_5V_Y17 (power), Y18 GND_Y18 (power), Y19 NC_Y19, Y20 NC_Y20

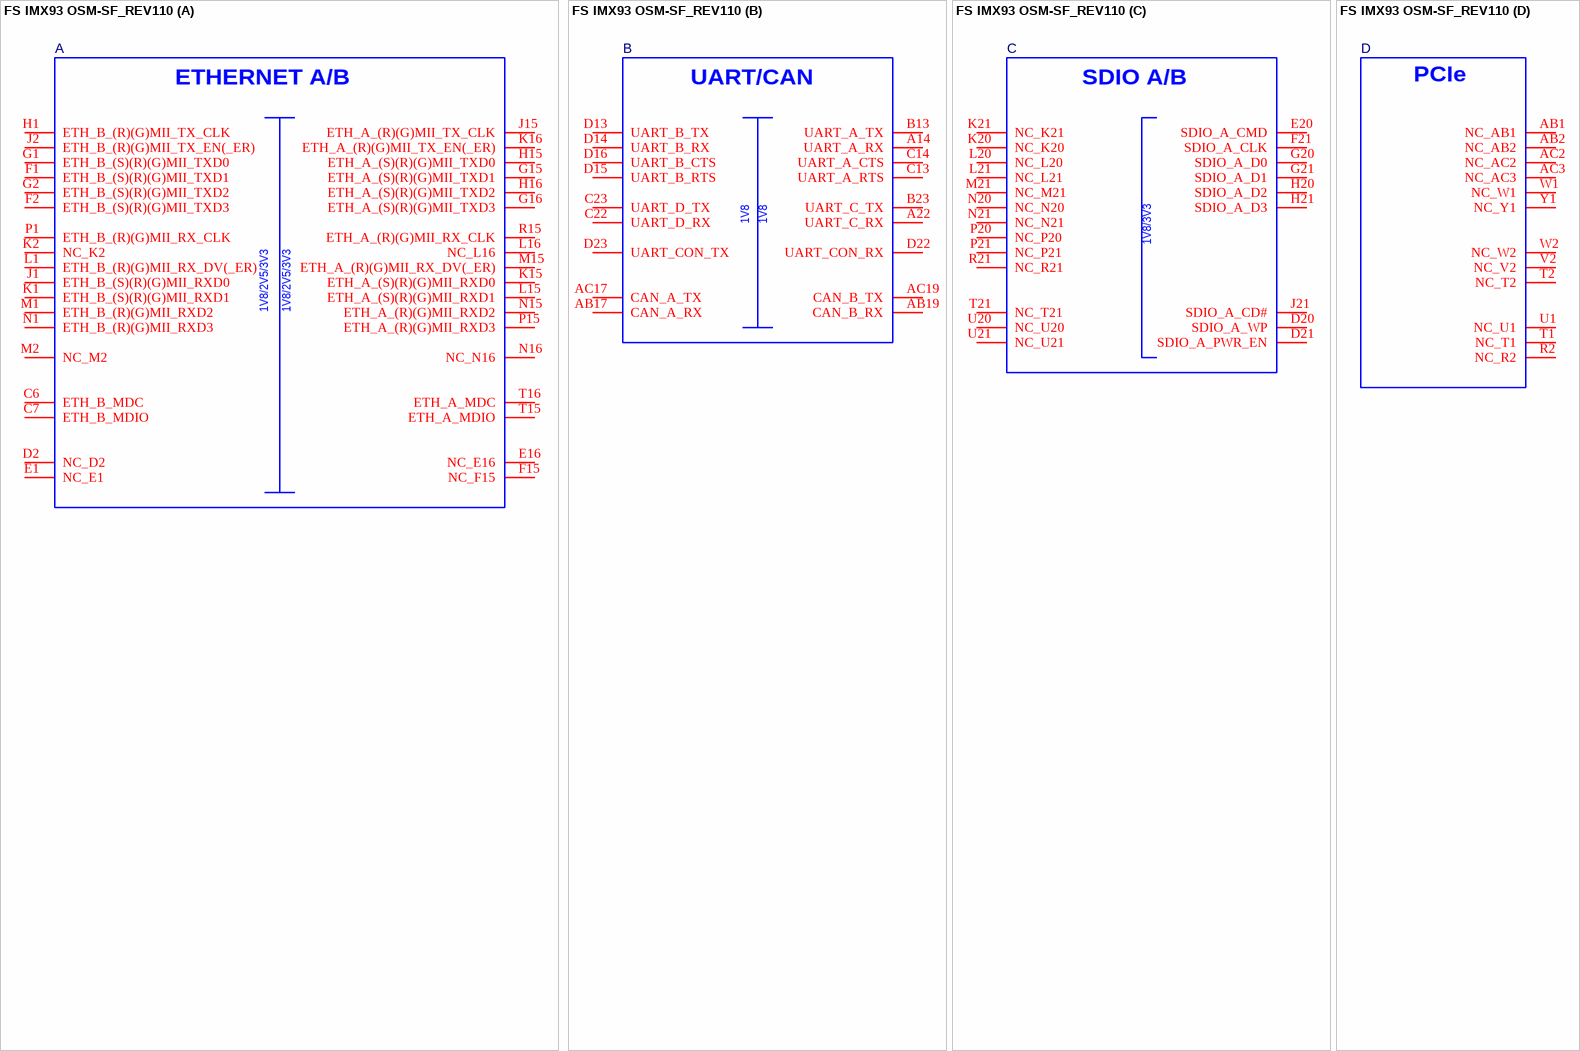
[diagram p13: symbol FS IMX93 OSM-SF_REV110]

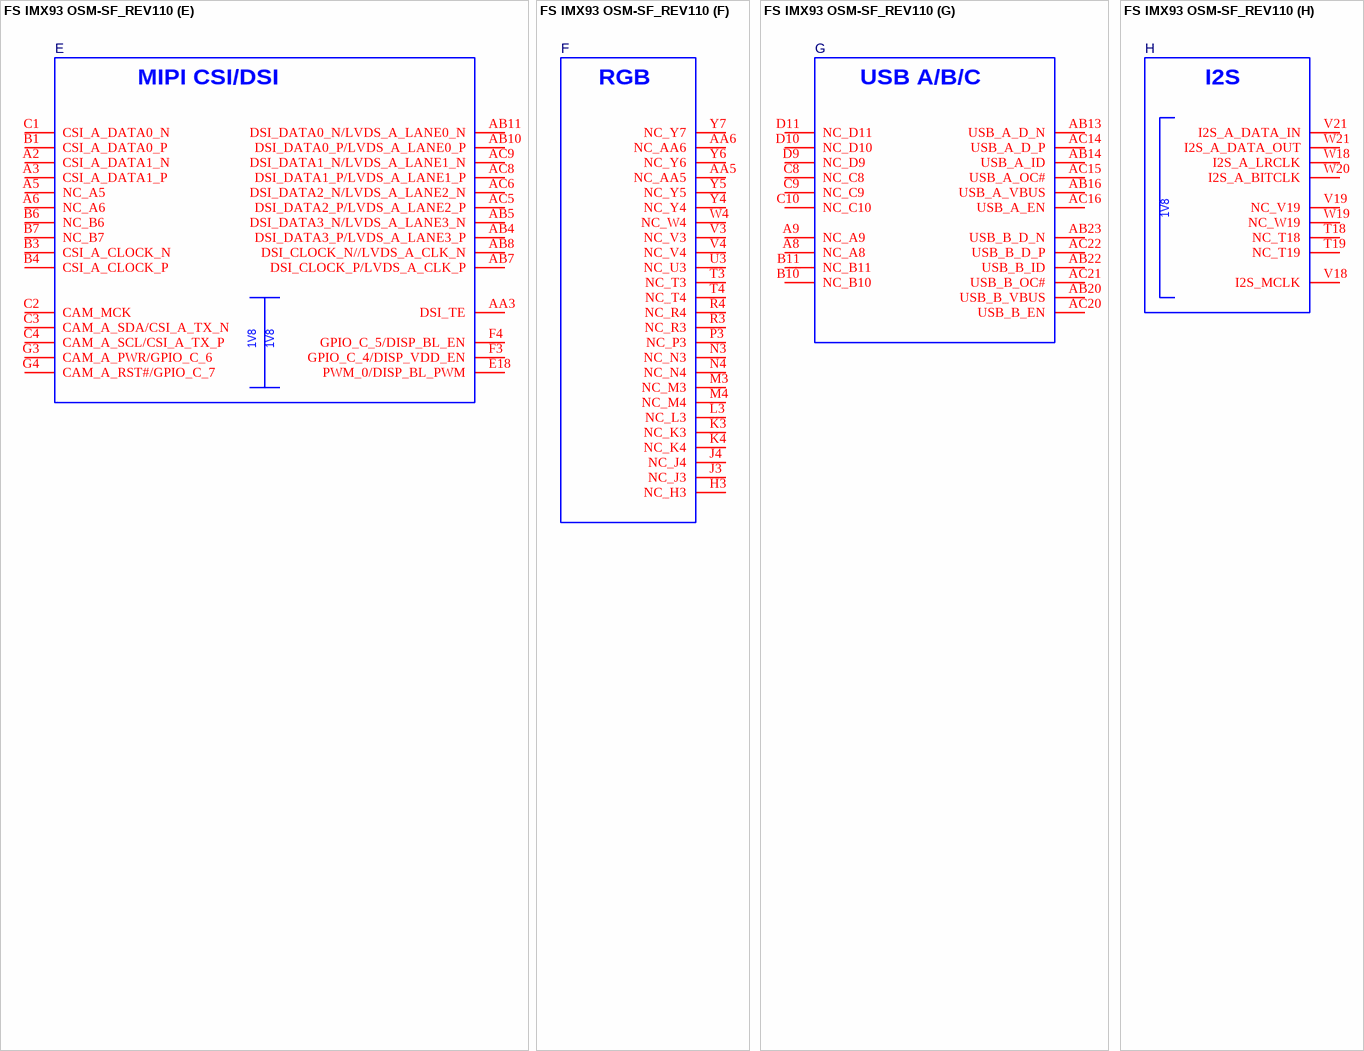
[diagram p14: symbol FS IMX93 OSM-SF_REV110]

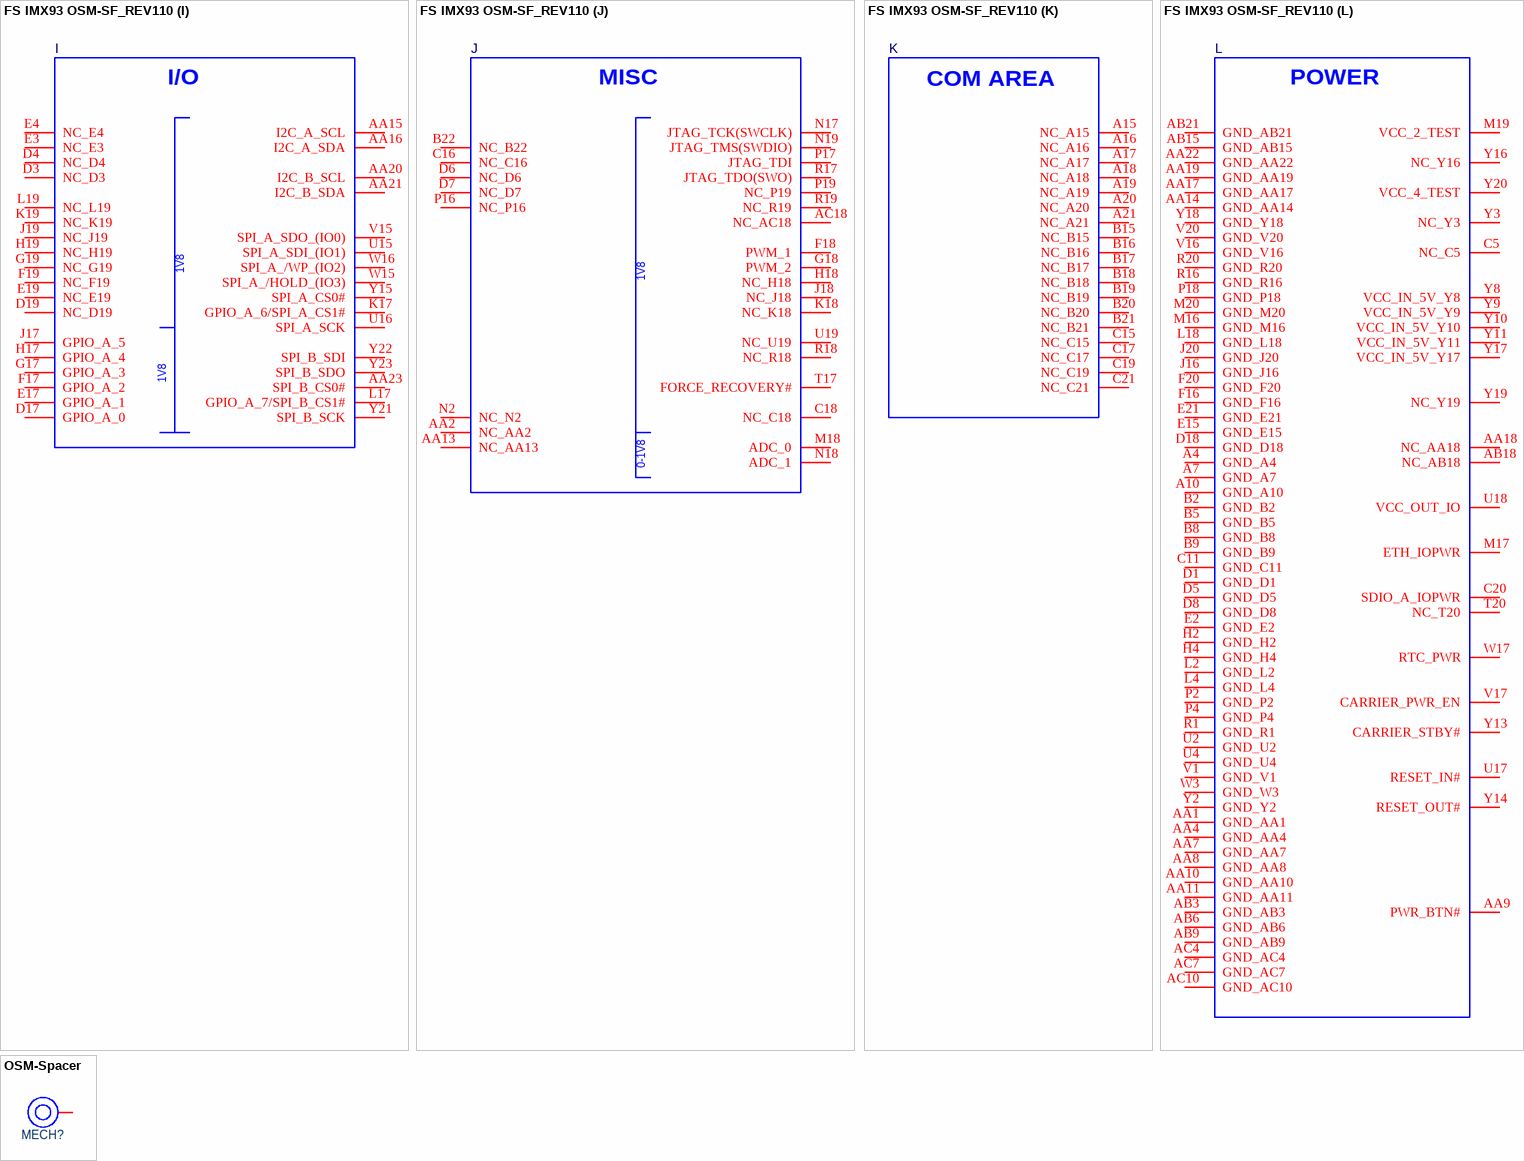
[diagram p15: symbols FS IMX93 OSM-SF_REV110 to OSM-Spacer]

## FS IMX93 OSM-SF_REV110
designator ?  (value not drawn)
part A pins: C6 ETH_B_MDC, C7 ETH_B_MDIO, D2 NC_D2, E1 NC_E1, E16 NC_E16, F1 ETH_B_(S)(R)(G)MII_TXD1, F2 ETH_B_(S)(R)(G)MII_TXD3, F15 NC_F15, G1 ETH_B_(S)(R)(G)MII_TXD0, G2 ETH_B_(S)(R)(G)MII_TXD2, G15 ETH_A_(S)(R)(G)MII_TXD1, G16 ETH_A_(S)(R)(G)MII_TXD3, H1 ETH_B_(R)(G)MII_TX_CLK, H15 ETH_A_(S)(R)(G)MII_TXD0, H16 ETH_A_(S)(R)(G)MII_TXD2, J1 ETH_B_(S)(R)(G)MII_RXD0, J2 ETH_B_(R)(G)MII_TX_EN(_ER), J15 ETH_A_(R)(G)MII_TX_CLK, K1 ETH_B_(S)(R)(G)MII_RXD1, K2 NC_K2, K15 ETH_A_(S)(R)(G)MII_RXD0, K16 ETH_A_(R)(G)MII_TX_EN(_ER), L1 ETH_B_(R)(G)MII_RX_DV(_ER), L15 ETH_A_(S)(R)(G)MII_RXD1, L16 NC_L16, M1 ETH_B_(R)(G)MII_RXD2, M2 NC_M2, M15 ETH_A_(R)(G)MII_RX_DV(_ER), N1 ETH_B_(R)(G)MII_RXD3, N15 ETH_A_(R)(G)MII_RXD2, N16 NC_N16, P1 ETH_B_(R)(G)MII_RX_CLK, P15 ETH_A_(R)(G)MII_RXD3, R15 ETH_A_(R)(G)MII_RX_CLK, T15 ETH_A_MDIO, T16 ETH_A_MDC
part B pins: A14 UART_A_RX, A22 UART_C_RX, AB17 CAN_A_RX, AB19 CAN_B_RX, AC17 CAN_A_TX, AC19 CAN_B_TX, B13 UART_A_TX, B23 UART_C_TX, C13 UART_A_RTS, C14 UART_A_CTS, C22 UART_D_RX, C23 UART_D_TX, D13 UART_B_TX, D14 UART_B_RX, D15 UART_B_RTS, D16 UART_B_CTS, D22 UART_CON_RX, D23 UART_CON_TX
part C pins: D20 SDIO_A_WP, D21 SDIO_A_PWR_EN, E20 SDIO_A_CMD, F21 SDIO_A_CLK, G20 SDIO_A_D0, G21 SDIO_A_D1, H20 SDIO_A_D2, H21 SDIO_A_D3, J21 SDIO_A_CD#, K20 NC_K20, K21 NC_K21, L20 NC_L20, L21 NC_L21, M21 NC_M21, N20 NC_N20, N21 NC_N21, P20 NC_P20, P21 NC_P21, R21 NC_R21, T21 NC_T21, U20 NC_U20, U21 NC_U21
part D pins: AB1 NC_AB1, AB2 NC_AB2, AC2 NC_AC2, AC3 NC_AC3, R2 NC_R2, T1 NC_T1, T2 NC_T2, U1 NC_U1, V2 NC_V2, W1 NC_W1, W2 NC_W2, Y1 NC_Y1
part E pins: A2 CSI_A_DATA1_N, A3 CSI_A_DATA1_P, A5 NC_A5, A6 NC_A6, AA3 DSI_TE, AB4 DSI_DATA3_P/LVDS_A_LANE3_P, AB5 DSI_DATA3_N/LVDS_A_LANE3_N, AB7 DSI_CLOCK_P/LVDS_A_CLK_P, AB8 DSI_CLOCK_N//LVDS_A_CLK_N, AB10 DSI_DATA0_P/LVDS_A_LANE0_P, AB11 DSI_DATA0_N/LVDS_A_LANE0_N, AC5 DSI_DATA2_P/LVDS_A_LANE2_P, AC6 DSI_DATA2_N/LVDS_A_LANE2_N, AC8 DSI_DATA1_P/LVDS_A_LANE1_P, AC9 DSI_DATA1_N/LVDS_A_LANE1_N, B1 CSI_A_DATA0_P, B3 CSI_A_CLOCK_N, B4 CSI_A_CLOCK_P, B6 NC_B6, B7 NC_B7, C1 CSI_A_DATA0_N, C2 CAM_MCK, C3 CAM_A_SDA/CSI_A_TX_N, C4 CAM_A_SCL/CSI_A_TX_P, E18 PWM_0/DISP_BL_PWM, F3 GPIO_C_4/DISP_VDD_EN, F4 GPIO_C_5/DISP_BL_EN, G3 CAM_A_PWR/GPIO_C_6, G4 CAM_A_RST#/GPIO_C_7
part F pins: AA5 NC_AA5, AA6 NC_AA6, H3 NC_H3, J3 NC_J3, J4 NC_J4, K3 NC_K3, K4 NC_K4, L3 NC_L3, M3 NC_M3, M4 NC_M4, N3 NC_N3, N4 NC_N4, P3 NC_P3, R3 NC_R3, R4 NC_R4, T3 NC_T3, T4 NC_T4, U3 NC_U3, V3 NC_V3, V4 NC_V4, W4 NC_W4, Y4 NC_Y4, Y5 NC_Y5, Y6 NC_Y6, Y7 NC_Y7
part G pins: A8 NC_A8, A9 NC_A9, AB13 USB_A_D_N, AB14 USB_A_ID, AB16 USB_A_VBUS, AB20 USB_B_VBUS, AB22 USB_B_ID, AB23 USB_B_D_N, AC14 USB_A_D_P, AC15 USB_A_OC#, AC16 USB_A_EN, AC20 USB_B_EN, AC21 USB_B_OC#, AC22 USB_B_D_P, B10 NC_B10, B11 NC_B11, C8 NC_C8, C9 NC_C9, C10 NC_C10, D9 NC_D9, D10 NC_D10, D11 NC_D11
part H pins: T18 NC_T18, T19 NC_T19, V18 I2S_MCLK, V19 NC_V19, V21 I2S_A_DATA_IN, W18 I2S_A_LRCLK, W19 NC_W19, W20 I2S_A_BITCLK, W21 I2S_A_DATA_OUT
part I pins: AA15 I2C_A_SCL, AA16 I2C_A_SDA, AA20 I2C_B_SCL, AA21 I2C_B_SDA, AA23 SPI_B_CS0#, D3 NC_D3, D4 NC_D4, D17 GPIO_A_0, D19 NC_D19, E3 NC_E3, E4 NC_E4, E17 GPIO_A_1, E19 NC_E19, F17 GPIO_A_2, F19 NC_F19, G17 GPIO_A_3, G19 NC_G19, H17 GPIO_A_4, H19 NC_H19, J17 GPIO_A_5, J19 NC_J19, K17 GPIO_A_6/SPI_A_CS1#, K19 NC_K19, L17 GPIO_A_7/SPI_B_CS1#, L19 NC_L19, U15 SPI_A_SDI_(IO1), U16 SPI_A_SCK, V15 SPI_A_SDO_(IO0), W15 SPI_A_/HOLD_(IO3), W16 SPI_A_/WP_(IO2), Y15 SPI_A_CS0#, Y21 SPI_B_SCK, Y22 SPI_B_SDI, Y23 SPI_B_SDO
part J pins: AA2 NC_AA2, AA13 NC_AA13, AC18 NC_AC18, B22 NC_B22, C16 NC_C16, C18 NC_C18, D6 NC_D6, D7 NC_D7, F18 PWM_1, G18 PWM_2, H18 NC_H18, J18 NC_J18, K18 NC_K18, M18 ADC_0, N2 NC_N2, N17 JTAG_TCK(SWCLK), N18 ADC_1, N19 JTAG_TMS(SWDIO), P16 NC_P16, P17 JTAG_TDI, P19 NC_P19, R17 JTAG_TDO(SWO), R18 NC_R18, R19 NC_R19, T17 FORCE_RECOVERY#, U19 NC_U19
part K pins: A15 NC_A15, A16 NC_A16, A17 NC_A17, A18 NC_A18, A19 NC_A19, A20 NC_A20, A21 NC_A21, B15 NC_B15, B16 NC_B16, B17 NC_B17, B18 NC_B18, B19 NC_B19, B20 NC_B20, B21 NC_B21, C15 NC_C15, C17 NC_C17, C19 NC_C19, C21 NC_C21
part L pins: A4 GND_A4 (power), A7 GND_A7 (power), A10 GND_A10 (power), AA1 GND_AA1 (power), AA4 GND_AA4 (power), AA7 GND_AA7 (power), AA8 GND_AA8 (power), AA9 PWR_BTN#, AA10 GND_AA10 (power), AA11 GND_AA11 (power), AA14 GND_AA14 (power), AA17 GND_AA17 (power), AA18 NC_AA18, AA19 GND_AA19 (power), AA22 GND_AA22 (power), AB3 GND_AB3 (power), AB6 GND_AB6 (power), AB9 GND_AB9 (power), AB15 GND_AB15 (power), AB18 NC_AB18, AB21 GND_AB21 (power), AC4 GND_AC4 (power), AC7 GND_AC7 (power), AC10 GND_AC10 (power), B2 GND_B2 (power), B5 GND_B5 (power), B8 GND_B8 (power), B9 GND_B9 (power), C5 NC_C5, C11 GND_C11 (power), C20 SDIO_A_IOPWR, D1 GND_D1 (power), D5 GND_D5 (power), D8 GND_D8 (power), D18 GND_D18 (power), E2 GND_E2 (power), E15 GND_E15 (power), E21 GND_E21 (power), F16 GND_F16 (power), F20 GND_F20 (power), H2 GND_H2 (power), H4 GND_H4 (power), J16 GND_J16 (power), J20 GND_J20 (power), L2 GND_L2 (power), L4 GND_L4 (power), L18 GND_L18 (power), M16 GND_M16 (power), M17 ETH_IOPWR (power), M19 VCC_2_TEST, M20 GND_M20 (power), P2 GND_P2 (power), P4 GND_P4 (power), P18 GND_P18 (power), R1 GND_R1 (power), R16 GND_R16 (power), R20 GND_R20 (power), T20 NC_T20, U2 GND_U2 (power), U4 GND_U4 (power), U17 RESET_IN#, U18 VCC_OUT_IO, V1 GND_V1 (power), V16 GND_V16 (power), V17 CARRIER_PWR_EN, V20 GND_V20 (power), W3 GND_W3 (power), W17 RTC_PWR (power), Y2 GND_Y2 (power), Y3 NC_Y3, Y8 VCC_IN_5V_Y8 (power), Y9 VCC_IN_5V_Y9 (power), Y10 VCC_IN_5V_Y10 (power), Y11 VCC_IN_5V_Y11 (power), Y13 CARRIER_STBY#, Y14 RESET_OUT#, Y16 NC_Y16, Y17 VCC_IN_5V_Y17 (power), Y18 GND_Y18 (power), Y19 NC_Y19, Y20 VCC_4_TEST

## OSM-Spacer
designator MECH?, comment M2.5 x 3mm  (value not drawn)
WA-SMSI SMT Steel Spacer with internal Thread, OD 5.1mm, M2.5 x 3mm; Manufacturer Part Number: 9774030151R; Manufacturer: Wurth Elektronik; Inside Diameter: 3.5mm; Surface: Tin
footprint 9774030151
pins: 1

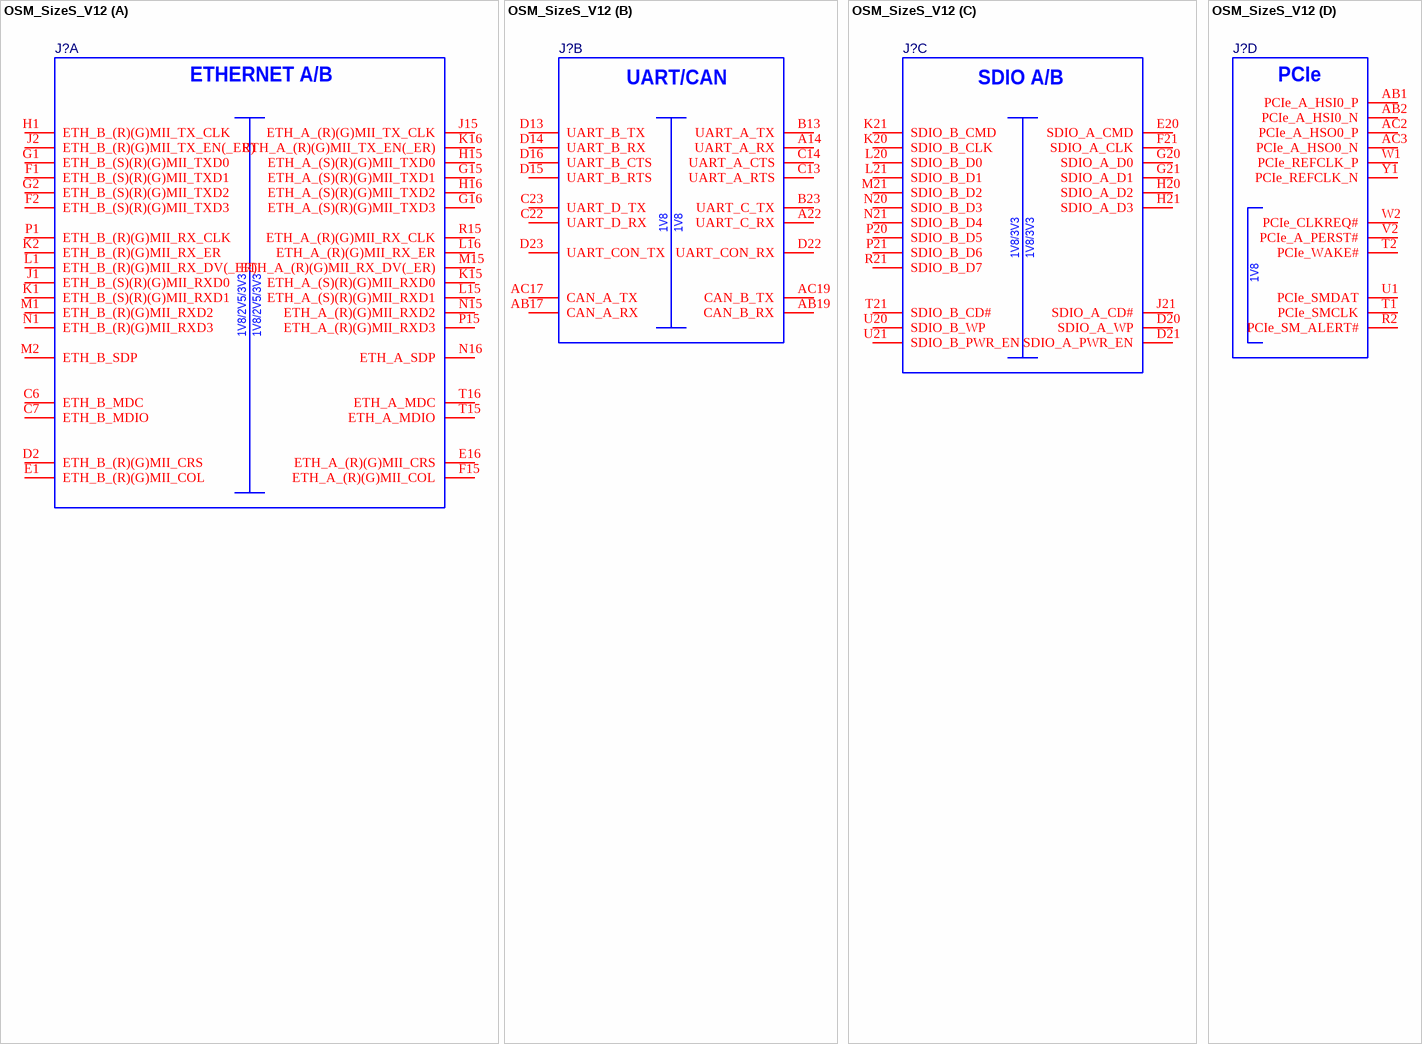
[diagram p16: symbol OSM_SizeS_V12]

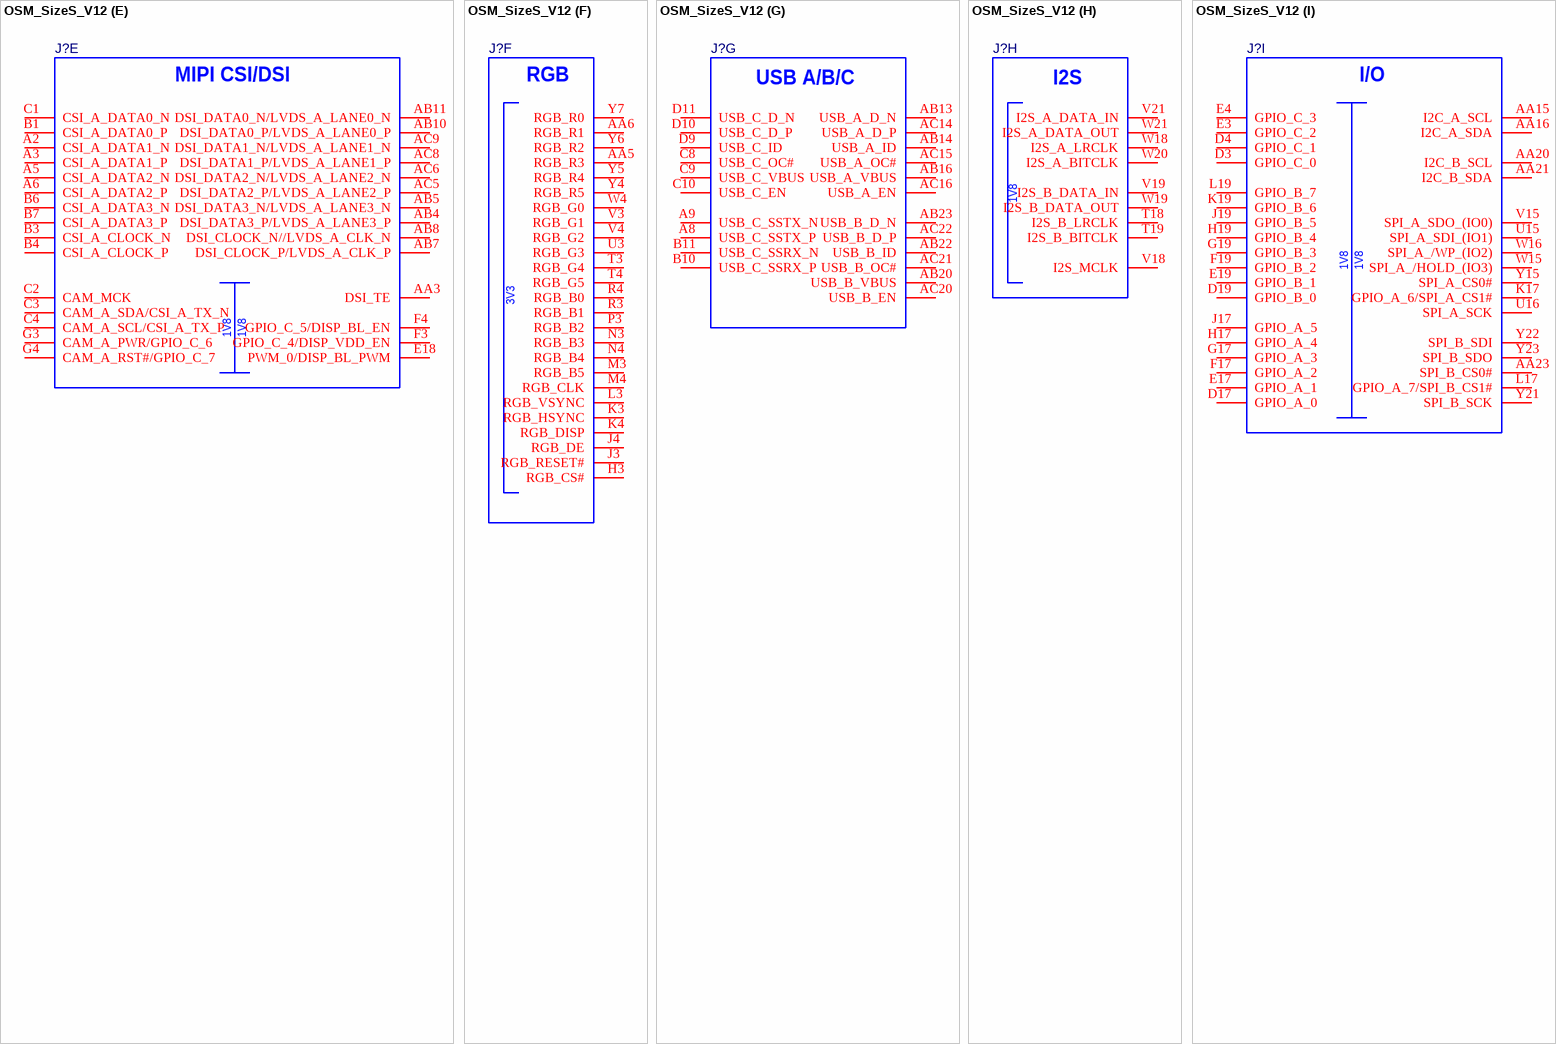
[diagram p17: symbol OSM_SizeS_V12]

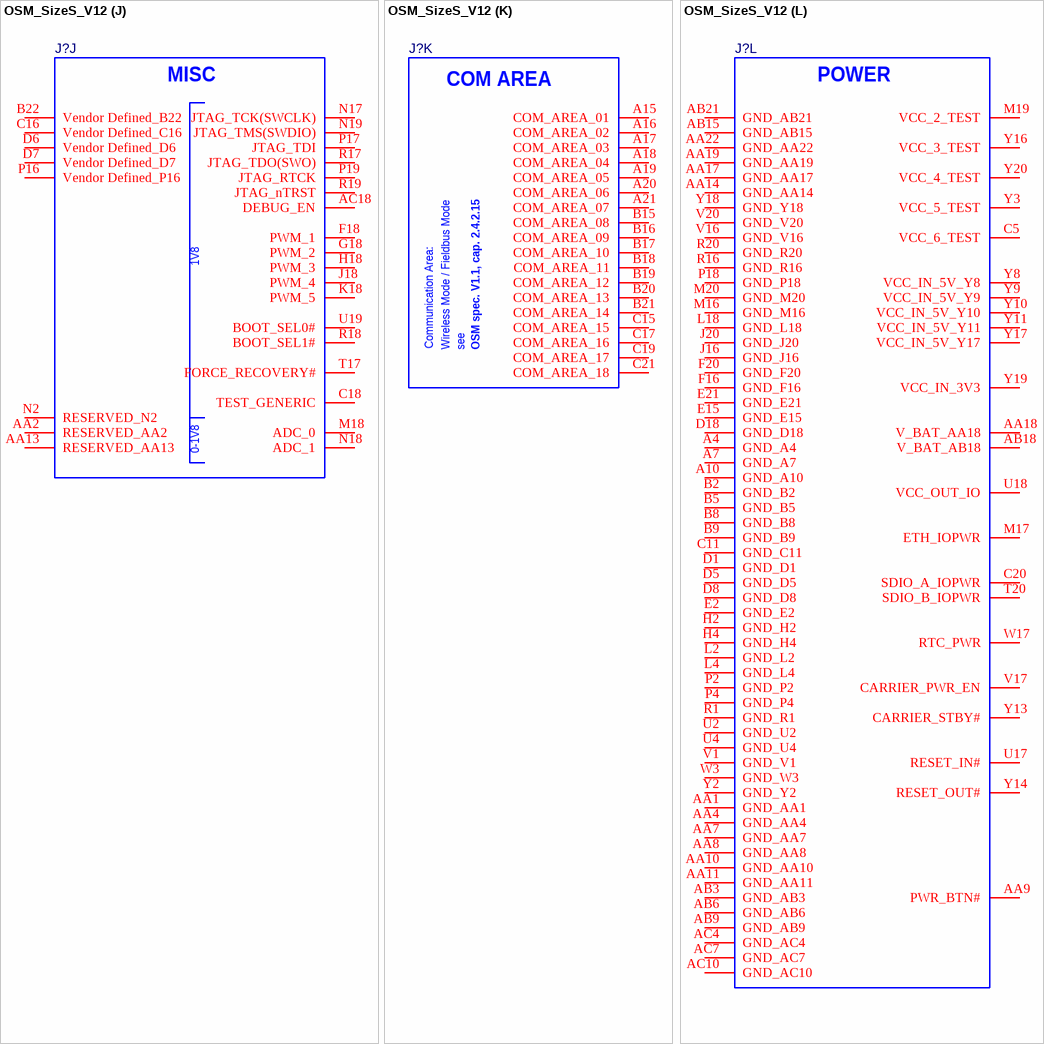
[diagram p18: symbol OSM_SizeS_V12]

## OSM_SizeS_V12
designator J?
part A pins: C6 ETH_B_MDC, C7 ETH_B_MDIO, D2 ETH_B_(R)(G)MII_CRS, E1 ETH_B_(R)(G)MII_COL, E16 ETH_A_(R)(G)MII_CRS, F1 ETH_B_(S)(R)(G)MII_TXD1, F2 ETH_B_(S)(R)(G)MII_TXD3, F15 ETH_A_(R)(G)MII_COL, G1 ETH_B_(S)(R)(G)MII_TXD0, G2 ETH_B_(S)(R)(G)MII_TXD2, G15 ETH_A_(S)(R)(G)MII_TXD1, G16 ETH_A_(S)(R)(G)MII_TXD3, H1 ETH_B_(R)(G)MII_TX_CLK, H15 ETH_A_(S)(R)(G)MII_TXD0, H16 ETH_A_(S)(R)(G)MII_TXD2, J1 ETH_B_(S)(R)(G)MII_RXD0, J2 ETH_B_(R)(G)MII_TX_EN(_ER), J15 ETH_A_(R)(G)MII_TX_CLK, K1 ETH_B_(S)(R)(G)MII_RXD1, K2 ETH_B_(R)(G)MII_RX_ER, K15 ETH_A_(S)(R)(G)MII_RXD0, K16 ETH_A_(R)(G)MII_TX_EN(_ER), L1 ETH_B_(R)(G)MII_RX_DV(_ER), L15 ETH_A_(S)(R)(G)MII_RXD1, L16 ETH_A_(R)(G)MII_RX_ER, M1 ETH_B_(R)(G)MII_RXD2, M2 ETH_B_SDP, M15 ETH_A_(R)(G)MII_RX_DV(_ER), N1 ETH_B_(R)(G)MII_RXD3, N15 ETH_A_(R)(G)MII_RXD2, N16 ETH_A_SDP, P1 ETH_B_(R)(G)MII_RX_CLK, P15 ETH_A_(R)(G)MII_RXD3, R15 ETH_A_(R)(G)MII_RX_CLK, T15 ETH_A_MDIO, T16 ETH_A_MDC
part B pins: A14 UART_A_RX, A22 UART_C_RX, AB17 CAN_A_RX, AB19 CAN_B_RX, AC17 CAN_A_TX, AC19 CAN_B_TX, B13 UART_A_TX, B23 UART_C_TX, C13 UART_A_RTS, C14 UART_A_CTS, C22 UART_D_RX, C23 UART_D_TX, D13 UART_B_TX, D14 UART_B_RX, D15 UART_B_RTS, D16 UART_B_CTS, D22 UART_CON_RX, D23 UART_CON_TX
part C pins: D20 SDIO_A_WP, D21 SDIO_A_PWR_EN, E20 SDIO_A_CMD, F21 SDIO_A_CLK, G20 SDIO_A_D0, G21 SDIO_A_D1, H20 SDIO_A_D2, H21 SDIO_A_D3, J21 SDIO_A_CD#, K20 SDIO_B_CLK, K21 SDIO_B_CMD, L20 SDIO_B_D0, L21 SDIO_B_D1, M21 SDIO_B_D2, N20 SDIO_B_D3, N21 SDIO_B_D4, P20 SDIO_B_D5, P21 SDIO_B_D6, R21 SDIO_B_D7, T21 SDIO_B_CD#, U20 SDIO_B_WP, U21 SDIO_B_PWR_EN
part D pins: AB1 PCIe_A_HSI0_P, AB2 PCIe_A_HSI0_N, AC2 PCIe_A_HSO0_P, AC3 PCIe_A_HSO0_N, R2 PCIe_SM_ALERT#, T1 PCIe_SMCLK, T2 PCIe_WAKE#, U1 PCIe_SMDAT, V2 PCIe_A_PERST#, W1 PCIe_REFCLK_P, W2 PCIe_CLKREQ#, Y1 PCIe_REFCLK_N
part E pins: A2 CSI_A_DATA1_N, A3 CSI_A_DATA1_P, A5 CSI_A_DATA2_N, A6 CSI_A_DATA2_P, AA3 DSI_TE, AB4 DSI_DATA3_P/LVDS_A_LANE3_P, AB5 DSI_DATA3_N/LVDS_A_LANE3_N, AB7 DSI_CLOCK_P/LVDS_A_CLK_P, AB8 DSI_CLOCK_N//LVDS_A_CLK_N, AB10 DSI_DATA0_P/LVDS_A_LANE0_P, AB11 DSI_DATA0_N/LVDS_A_LANE0_N, AC5 DSI_DATA2_P/LVDS_A_LANE2_P, AC6 DSI_DATA2_N/LVDS_A_LANE2_N, AC8 DSI_DATA1_P/LVDS_A_LANE1_P, AC9 DSI_DATA1_N/LVDS_A_LANE1_N, B1 CSI_A_DATA0_P, B3 CSI_A_CLOCK_N, B4 CSI_A_CLOCK_P, B6 CSI_A_DATA3_N, B7 CSI_A_DATA3_P, C1 CSI_A_DATA0_N, C2 CAM_MCK, C3 CAM_A_SDA/CSI_A_TX_N, C4 CAM_A_SCL/CSI_A_TX_P, E18 PWM_0/DISP_BL_PWM, F3 GPIO_C_4/DISP_VDD_EN, F4 GPIO_C_5/DISP_BL_EN, G3 CAM_A_PWR/GPIO_C_6, G4 CAM_A_RST#/GPIO_C_7
part F pins: AA5 RGB_R3, AA6 RGB_R1, H3 RGB_CS#, J3 RGB_RESET#, J4 RGB_DE, K3 RGB_HSYNC, K4 RGB_DISP, L3 RGB_VSYNC, M3 RGB_B5, M4 RGB_CLK, N3 RGB_B3, N4 RGB_B4, P3 RGB_B2, R3 RGB_B1, R4 RGB_B0, T3 RGB_G4, T4 RGB_G5, U3 RGB_G3, V3 RGB_G1, V4 RGB_G2, W4 RGB_G0, Y4 RGB_R5, Y5 RGB_R4, Y6 RGB_R2, Y7 RGB_R0
part G pins: A8 USB_C_SSTX_P, A9 USB_C_SSTX_N, AB13 USB_A_D_N, AB14 USB_A_ID, AB16 USB_A_VBUS, AB20 USB_B_VBUS, AB22 USB_B_ID, AB23 USB_B_D_N, AC14 USB_A_D_P, AC15 USB_A_OC#, AC16 USB_A_EN, AC20 USB_B_EN, AC21 USB_B_OC#, AC22 USB_B_D_P, B10 USB_C_SSRX_P, B11 USB_C_SSRX_N, C8 USB_C_OC#, C9 USB_C_VBUS, C10 USB_C_EN, D9 USB_C_ID, D10 USB_C_D_P, D11 USB_C_D_N
part H pins: T18 I2S_B_LRCLK, T19 I2S_B_BITCLK, V18 I2S_MCLK, V19 I2S_B_DATA_IN, V21 I2S_A_DATA_IN, W18 I2S_A_LRCLK, W19 I2S_B_DATA_OUT, W20 I2S_A_BITCLK, W21 I2S_A_DATA_OUT
part I pins: AA15 I2C_A_SCL, AA16 I2C_A_SDA, AA20 I2C_B_SCL, AA21 I2C_B_SDA, AA23 SPI_B_CS0#, D3 GPIO_C_0, D4 GPIO_C_1, D17 GPIO_A_0, D19 GPIO_B_0, E3 GPIO_C_2, E4 GPIO_C_3, E17 GPIO_A_1, E19 GPIO_B_1, F17 GPIO_A_2, F19 GPIO_B_2, G17 GPIO_A_3, G19 GPIO_B_3, H17 GPIO_A_4, H19 GPIO_B_4, J17 GPIO_A_5, J19 GPIO_B_5, K17 GPIO_A_6/SPI_A_CS1#, K19 GPIO_B_6, L17 GPIO_A_7/SPI_B_CS1#, L19 GPIO_B_7, U15 SPI_A_SDI_(IO1), U16 SPI_A_SCK, V15 SPI_A_SDO_(IO0), W15 SPI_A_/HOLD_(IO3), W16 SPI_A_/WP_(IO2), Y15 SPI_A_CS0#, Y21 SPI_B_SCK, Y22 SPI_B_SDI, Y23 SPI_B_SDO
part J pins: AA2 RESERVED_AA2, AA13 RESERVED_AA13, AC18 DEBUG_EN, B22 Vendor Defined_B22, C16 Vendor Defined_C16, C18 TEST_GENERIC, D6 Vendor Defined_D6, D7 Vendor Defined_D7, F18 PWM_1, G18 PWM_2, H18 PWM_3, J18 PWM_4, K18 PWM_5, M18 ADC_0, N2 RESERVED_N2, N17 JTAG_TCK(SWCLK), N18 ADC_1, N19 JTAG_TMS(SWDIO), P16 Vendor Defined_P16, P17 JTAG_TDI, P19 JTAG_RTCK, R17 JTAG_TDO(SWO), R18 BOOT_SEL1#, R19 JTAG_nTRST, T17 FORCE_RECOVERY#, U19 BOOT_SEL0#
part K pins: A15 COM_AREA_01, A16 COM_AREA_02, A17 COM_AREA_03, A18 COM_AREA_04, A19 COM_AREA_05, A20 COM_AREA_06, A21 COM_AREA_07, B15 COM_AREA_08, B16 COM_AREA_09, B17 COM_AREA_10, B18 COM_AREA_11, B19 COM_AREA_12, B20 COM_AREA_13, B21 COM_AREA_14, C15 COM_AREA_15, C17 COM_AREA_16, C19 COM_AREA_17, C21 COM_AREA_18
part L pins: A4 GND_A4 (power), A7 GND_A7 (power), A10 GND_A10 (power), AA1 GND_AA1 (power), AA4 GND_AA4 (power), AA7 GND_AA7 (power), AA8 GND_AA8 (power), AA9 PWR_BTN#, AA10 GND_AA10 (power), AA11 GND_AA11 (power), AA14 GND_AA14 (power), AA17 GND_AA17 (power), AA18 V_BAT_AA18, AA19 GND_AA19 (power), AA22 GND_AA22 (power), AB3 GND_AB3 (power), AB6 GND_AB6 (power), AB9 GND_AB9 (power), AB15 GND_AB15 (power), AB18 V_BAT_AB18, AB21 GND_AB21 (power), AC4 GND_AC4 (power), AC7 GND_AC7 (power), AC10 GND_AC10 (power), B2 GND_B2 (power), B5 GND_B5 (power), B8 GND_B8 (power), B9 GND_B9 (power), C5 VCC_6_TEST, C11 GND_C11 (power), C20 SDIO_A_IOPWR, D1 GND_D1 (power), D5 GND_D5 (power), D8 GND_D8 (power), D18 GND_D18 (power), E2 GND_E2 (power), E15 GND_E15 (power), E21 GND_E21 (power), F16 GND_F16 (power), F20 GND_F20 (power), H2 GND_H2 (power), H4 GND_H4 (power), J16 GND_J16 (power), J20 GND_J20 (power), L2 GND_L2 (power), L4 GND_L4 (power), L18 GND_L18 (power), M16 GND_M16 (power), M17 ETH_IOPWR (power), M19 VCC_2_TEST, M20 GND_M20 (power), P2 GND_P2 (power), P4 GND_P4 (power), P18 GND_P18 (power), R1 GND_R1 (power), R16 GND_R16 (power), R20 GND_R20 (power), T20 SDIO_B_IOPWR, U2 GND_U2 (power), U4 GND_U4 (power), U17 RESET_IN#, U18 VCC_OUT_IO, V1 GND_V1 (power), V16 GND_V16 (power), V17 CARRIER_PWR_EN, V20 GND_V20 (power), W3 GND_W3 (power), W17 RTC_PWR (power), Y2 GND_Y2 (power), Y3 VCC_5_TEST, Y8 VCC_IN_5V_Y8 (power), Y9 VCC_IN_5V_Y9 (power), Y10 VCC_IN_5V_Y10 (power), Y11 VCC_IN_5V_Y11 (power), Y13 CARRIER_STBY#, Y14 RESET_OUT#, Y16 VCC_3_TEST, Y17 VCC_IN_5V_Y17 (power), Y18 GND_Y18 (power), Y19 VCC_IN_3V3, Y20 VCC_4_TEST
